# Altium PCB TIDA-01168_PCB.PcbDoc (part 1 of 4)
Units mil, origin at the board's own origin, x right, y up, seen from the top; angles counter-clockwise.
Board outline 7874.02 x 8344.02 mil, 4 copper layers (Top Layer, Signal Layer 1, Signal Layer 2, Bottom Layer), stack 65.748 mil thick; 480 components, 223 nets, 1266 pads, 1791 vias.
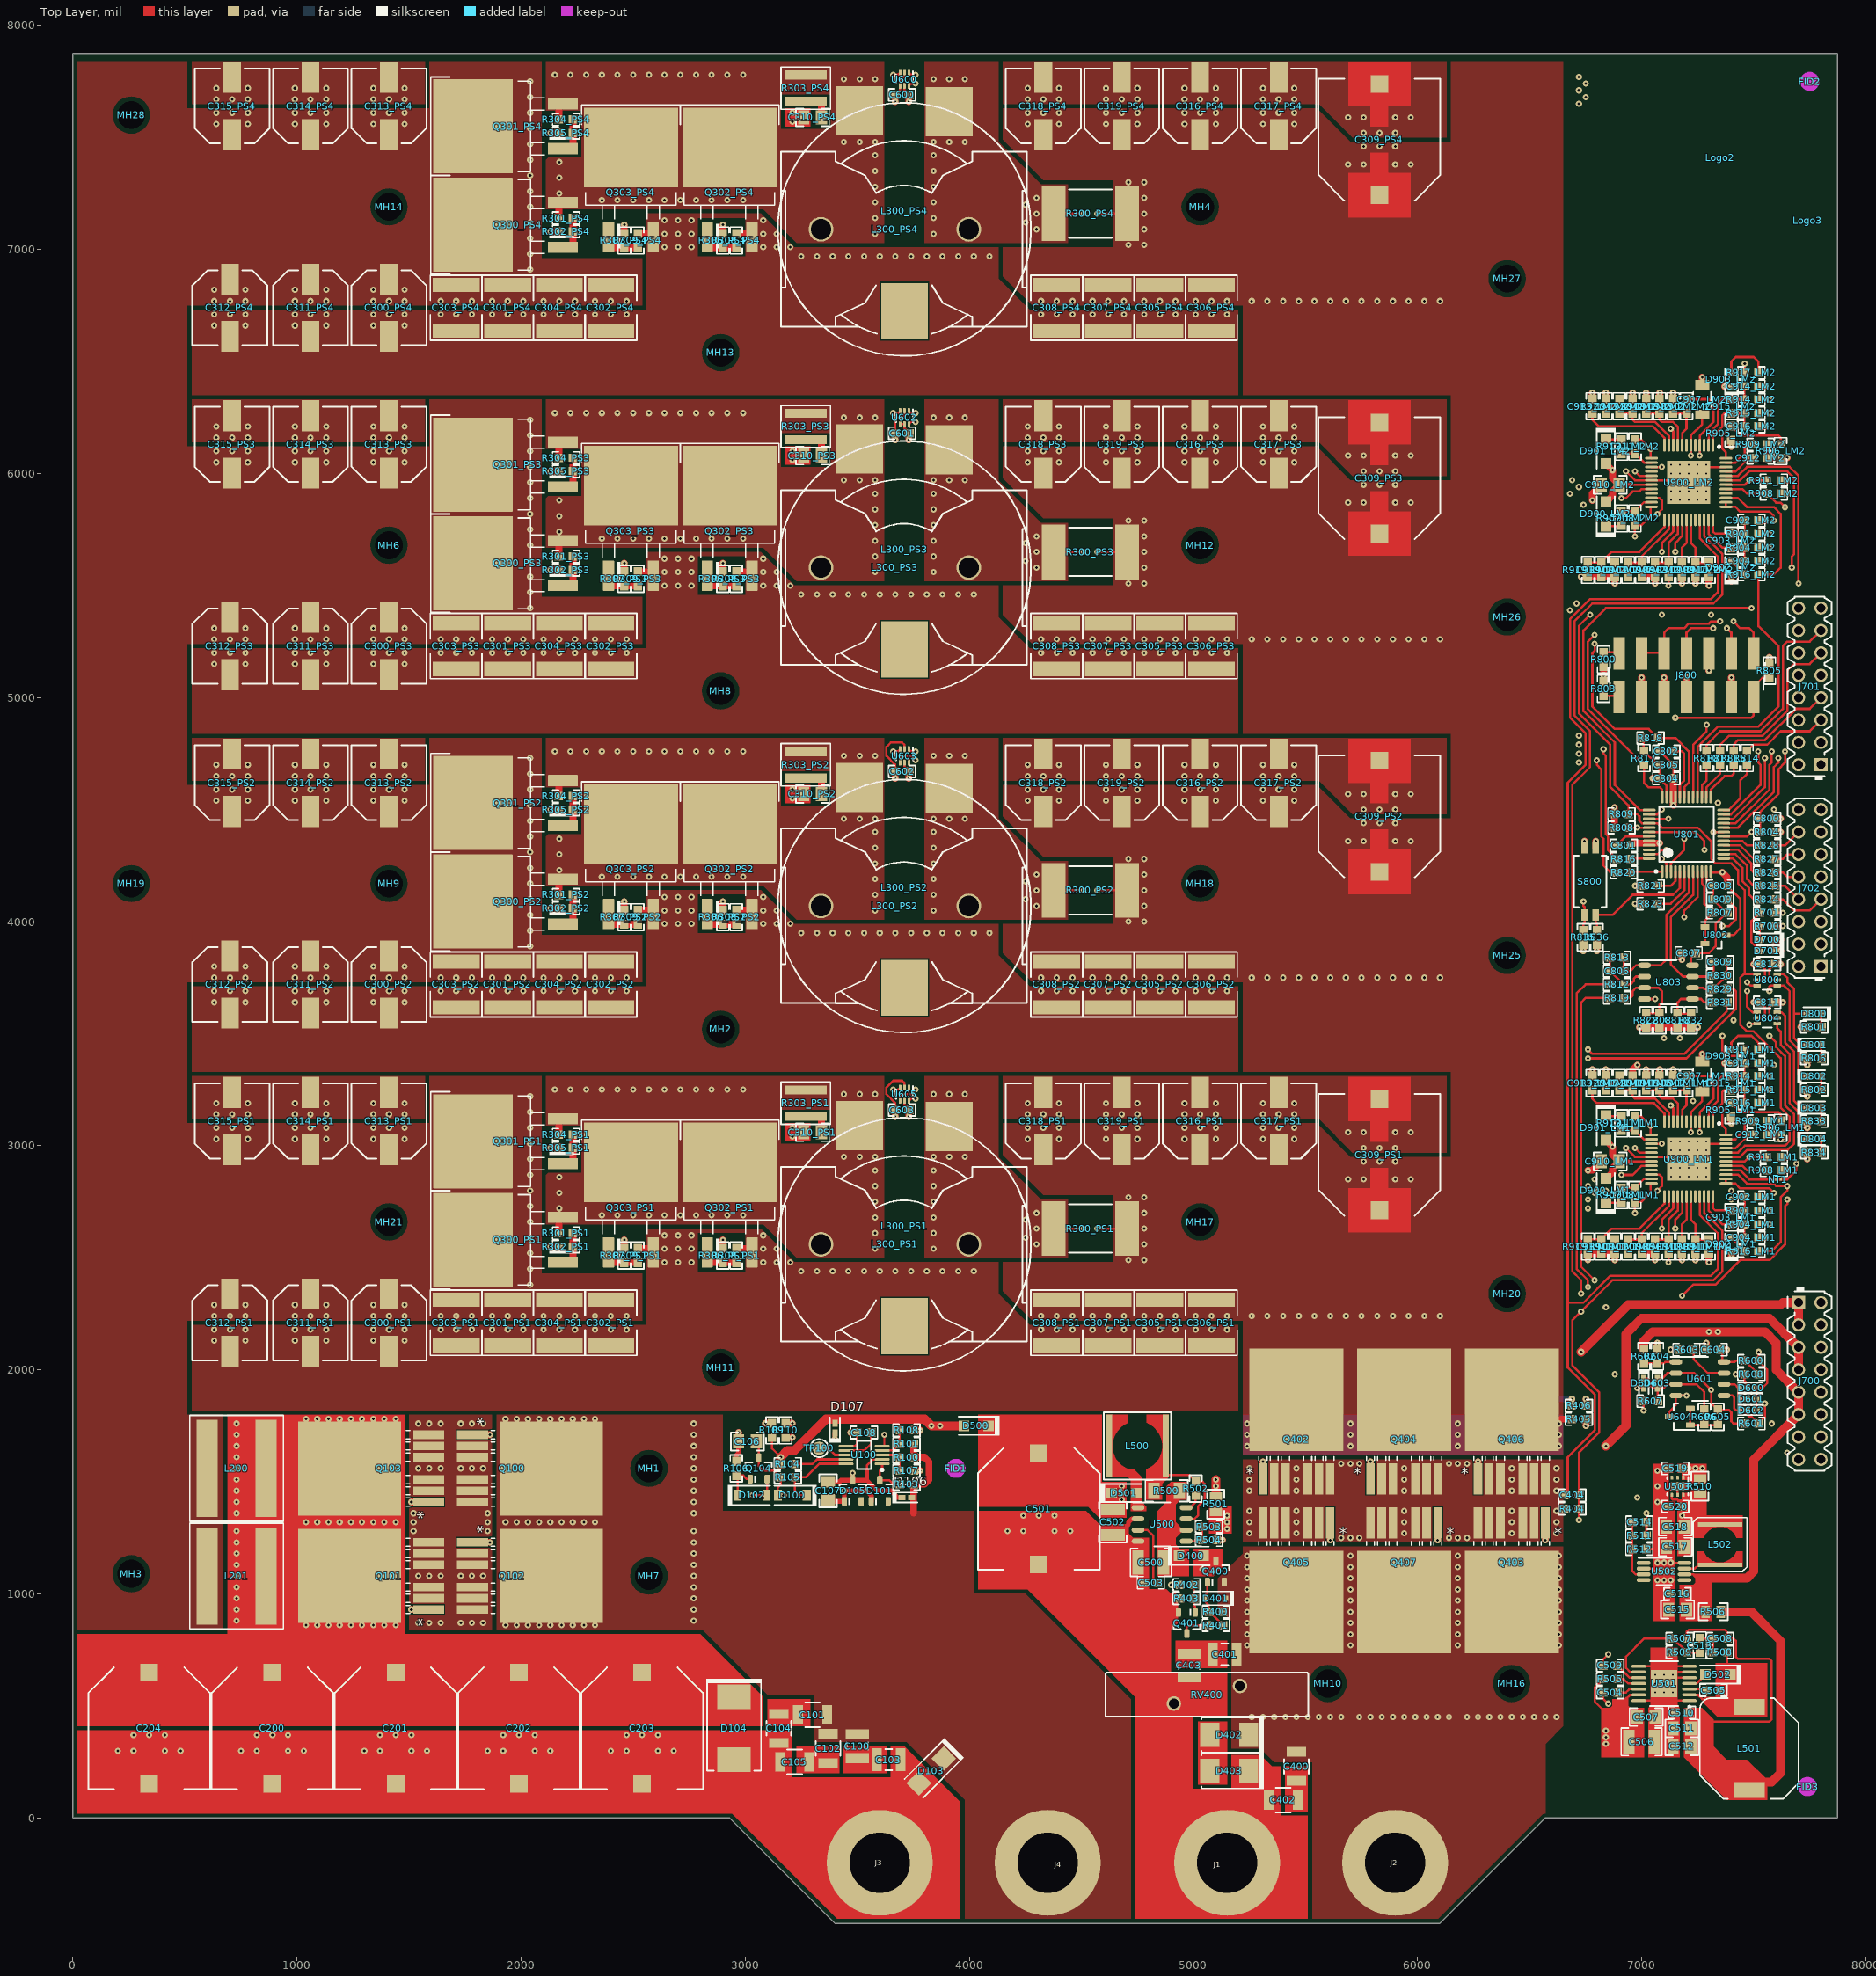
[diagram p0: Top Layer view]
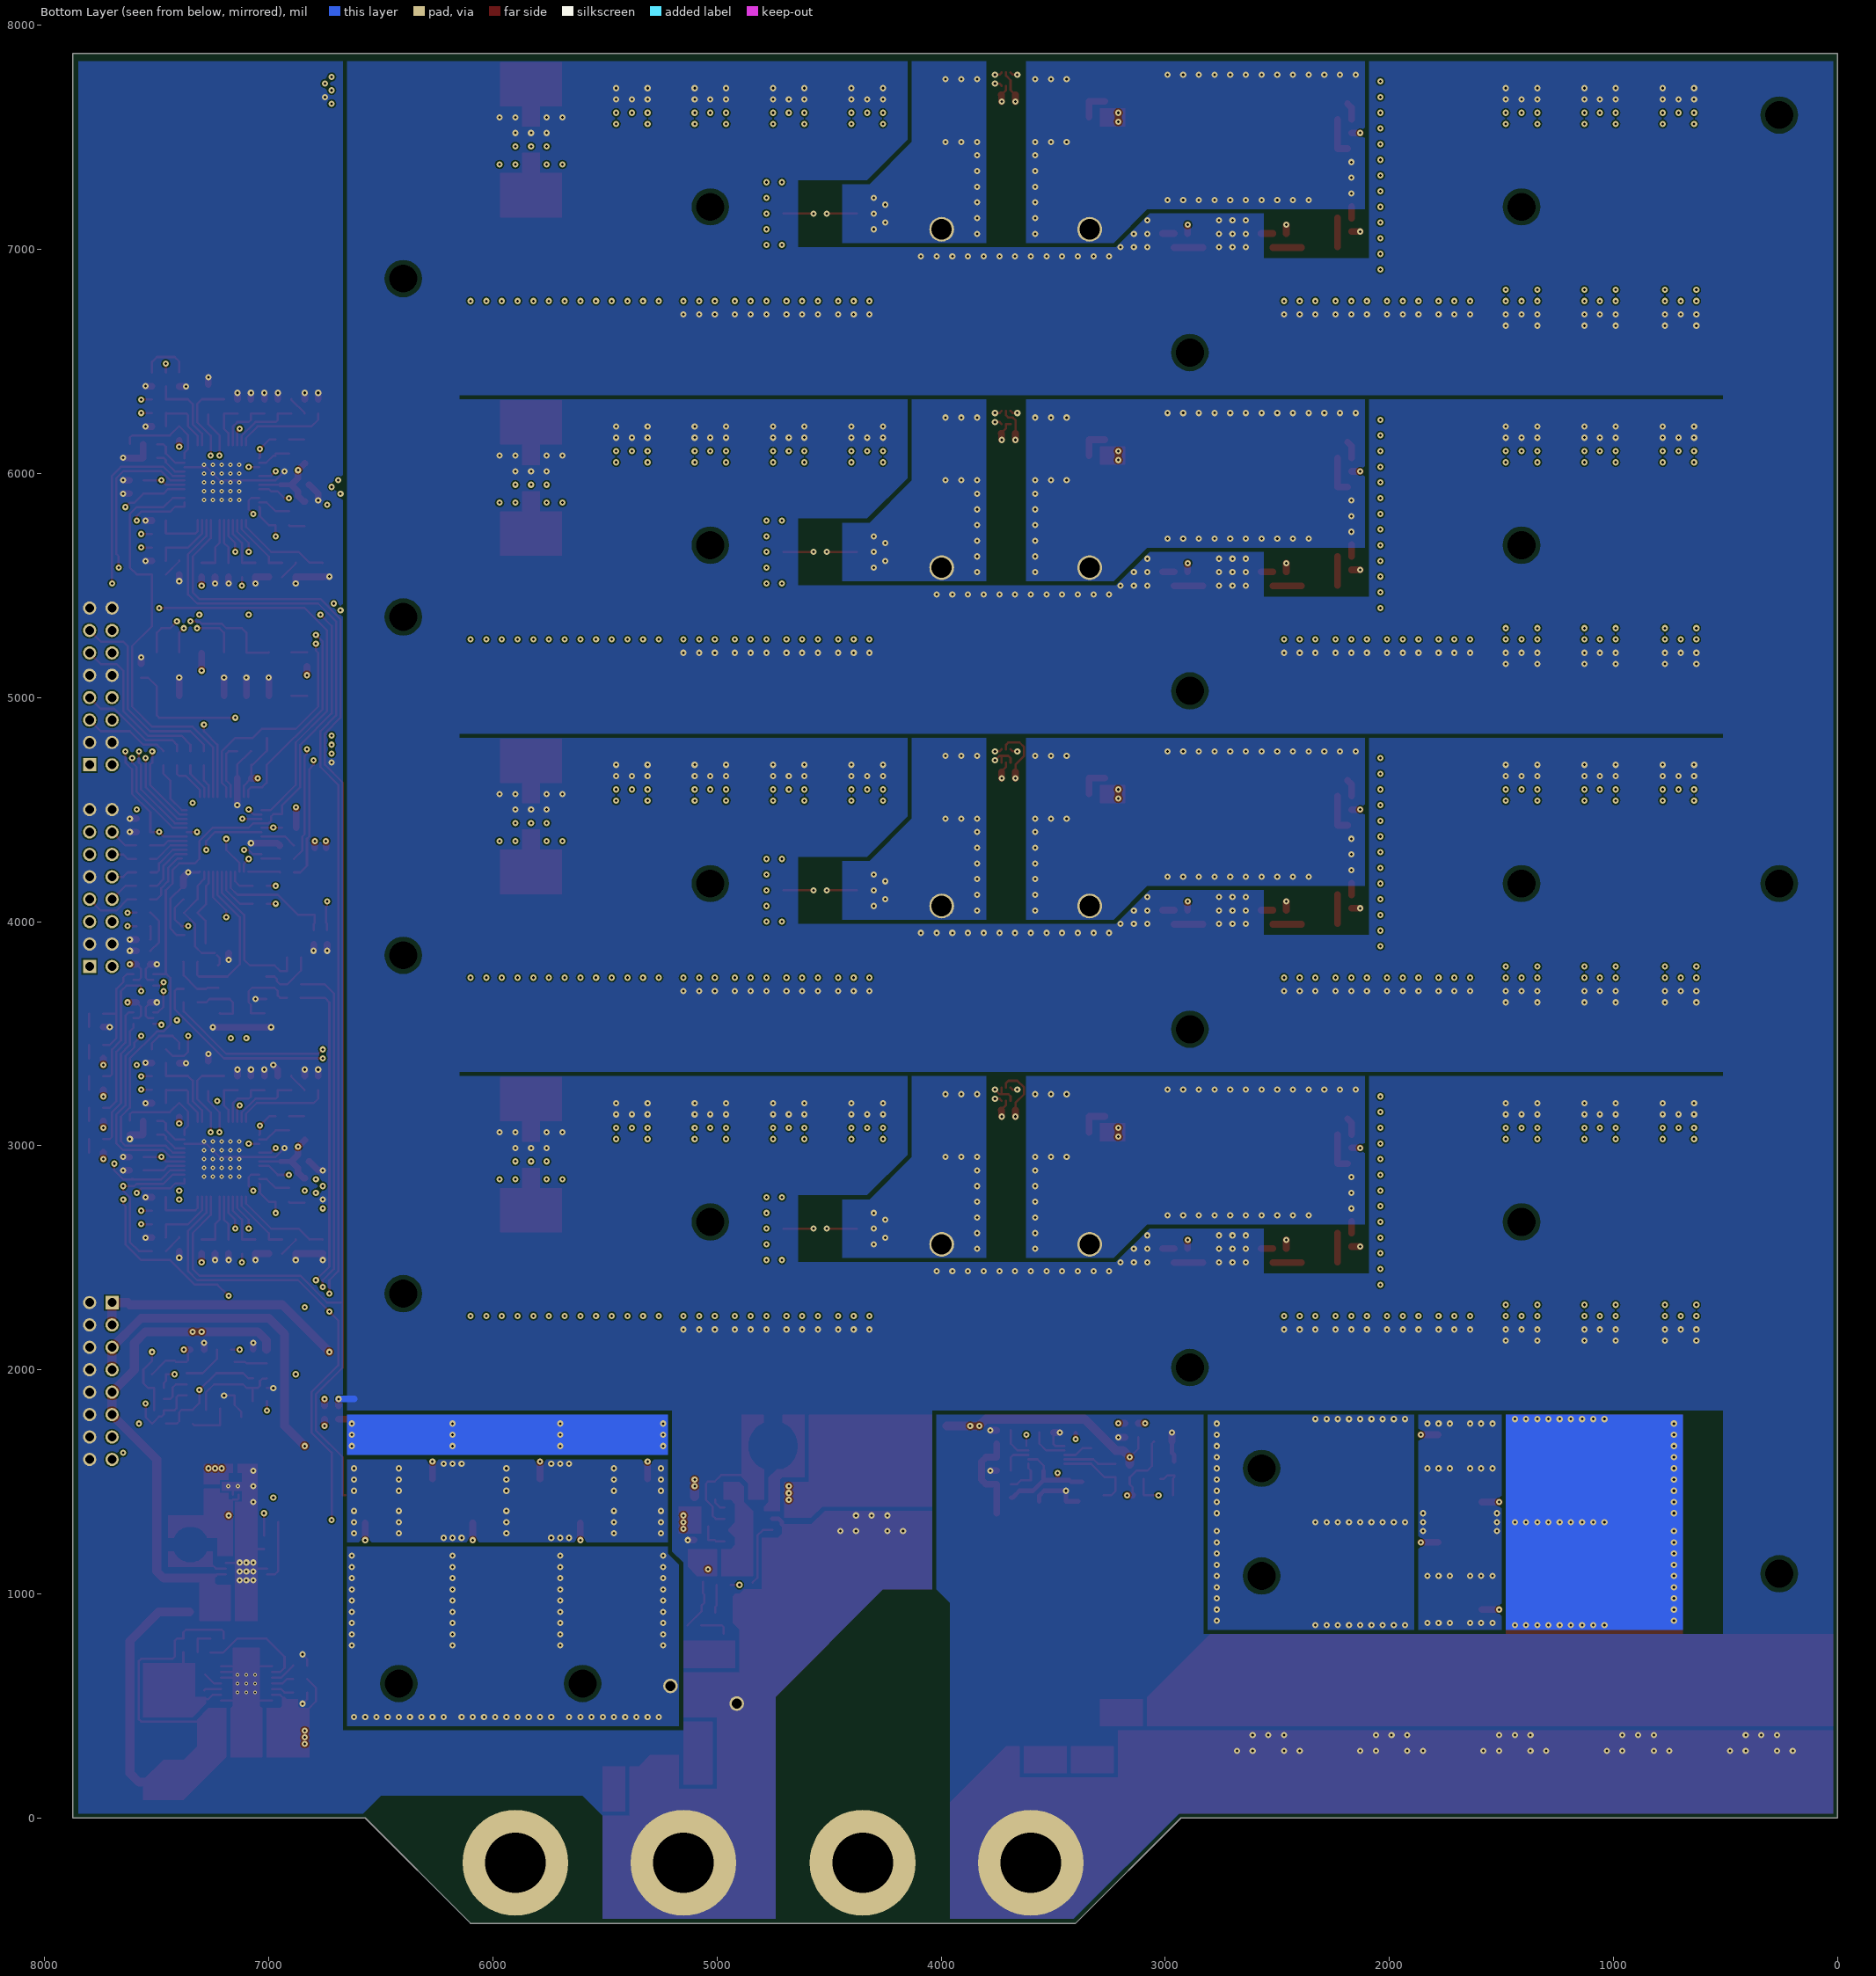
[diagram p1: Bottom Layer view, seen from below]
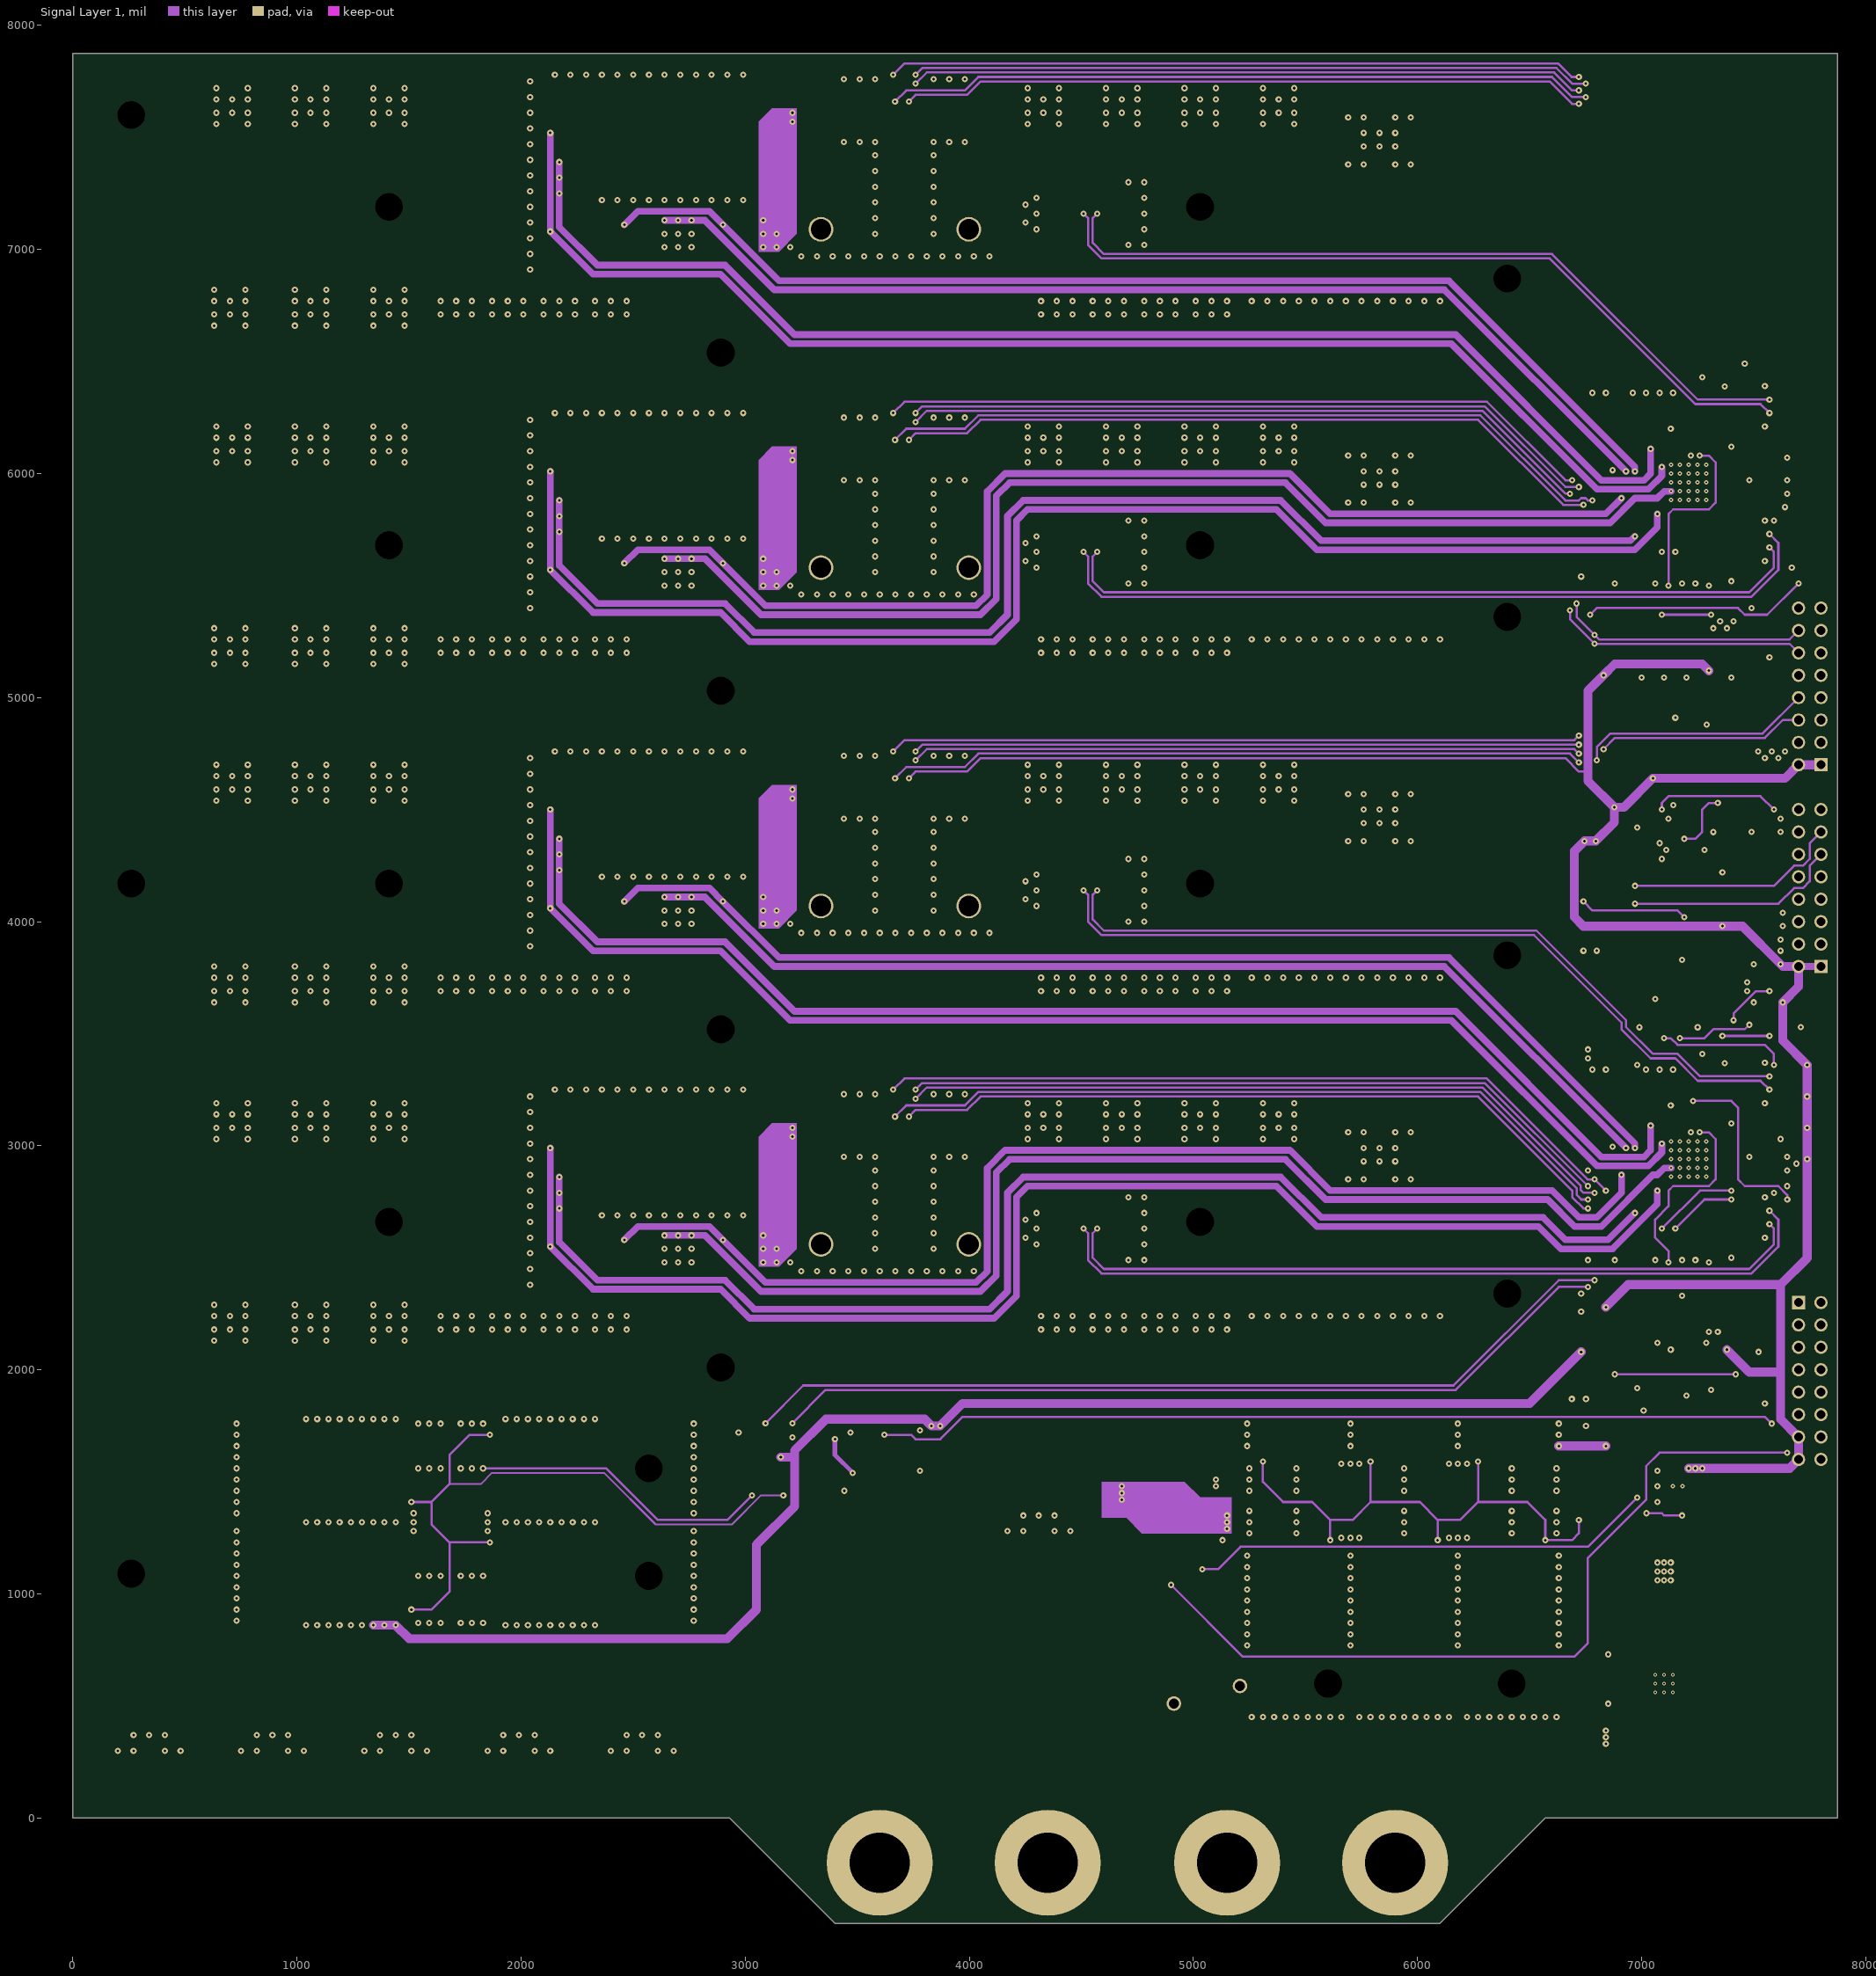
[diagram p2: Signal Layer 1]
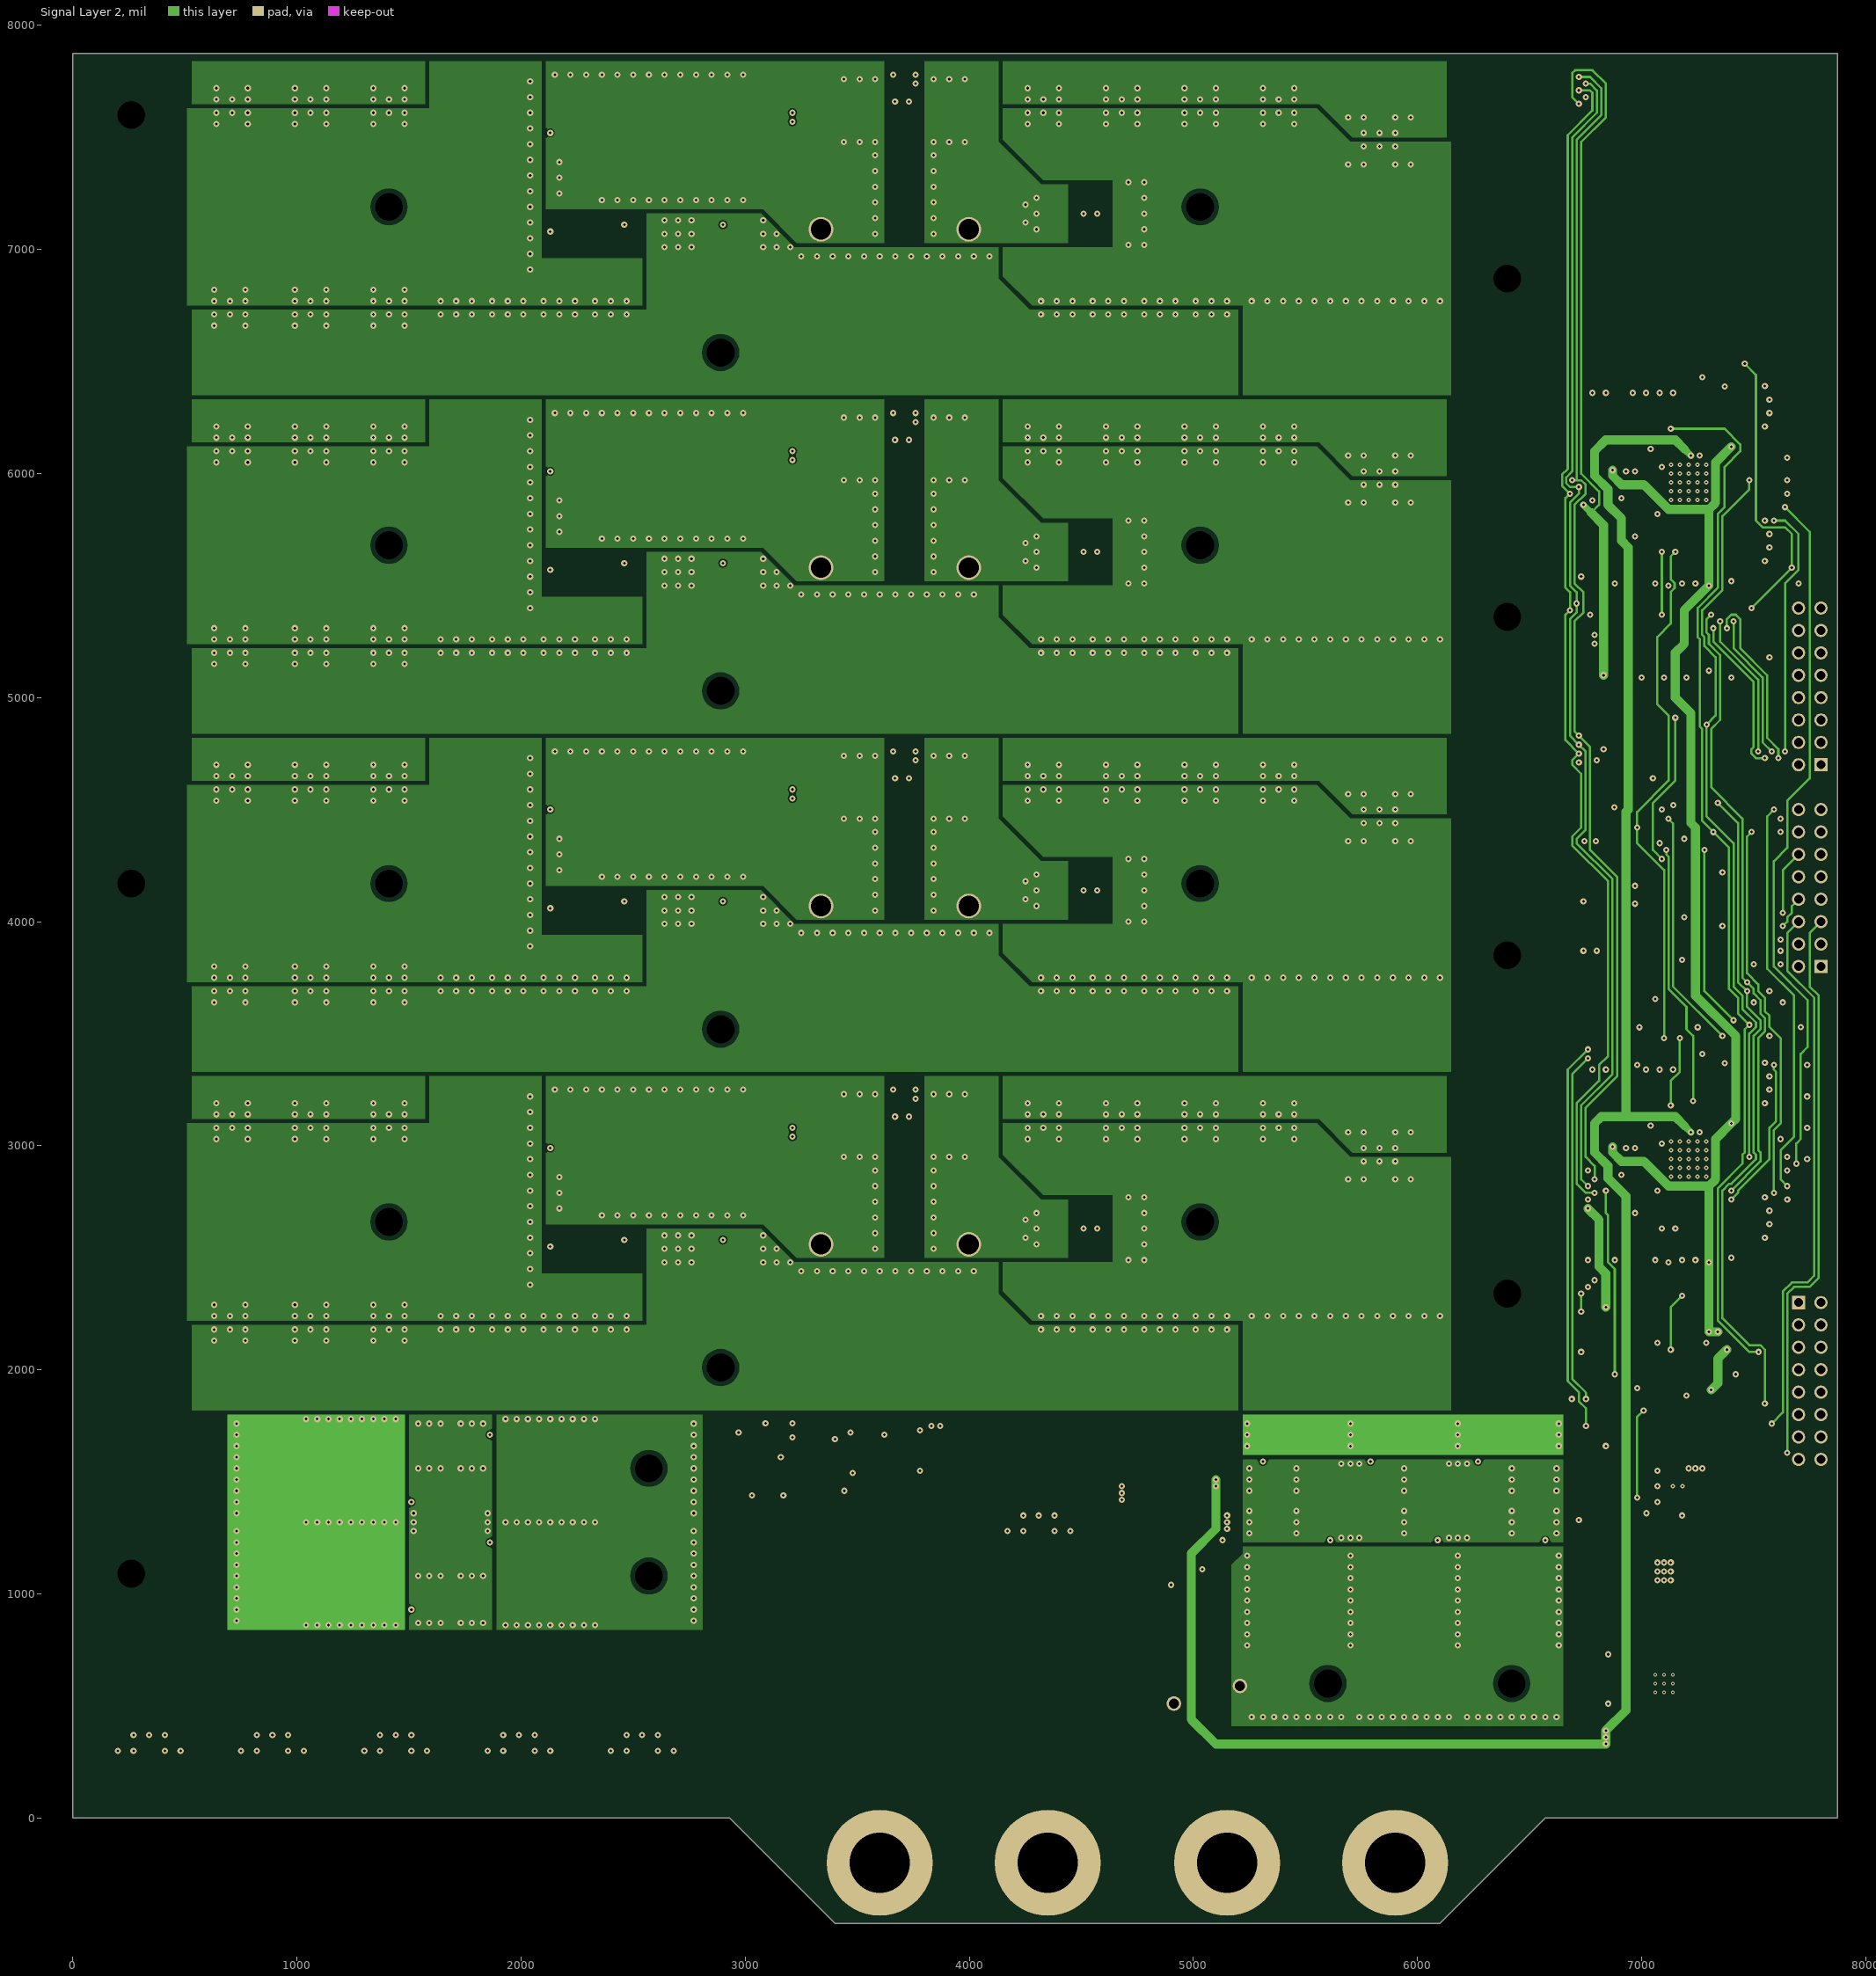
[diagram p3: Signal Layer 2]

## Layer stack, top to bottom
Top Solder: solder mask 0.4, Solder Resist, Dk 3.5
Top Layer: signal copper 3.7402
Dielectric1: prepreg 13.7795, 2x 7628, Dk 4.2
Signal Layer 1: signal copper 1.378
Dielectric 3: core 27.9528, FR-4, Dk 4.2
Signal Layer 2: signal copper 1.378
Dielectric 2: prepreg 13.7795, 2x 7628, Dk 4.2
Bottom Layer: signal copper 3.7402
Bottom Solder: solder mask 0.4, Solder Resist, Dk 3.5

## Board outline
0,0 2930,0 3400,-470 6100,-470 6570,0 7874.02,0 7874.02,7874.02 0,7874.02

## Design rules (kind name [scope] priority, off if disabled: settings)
AcuteAngle [All] p1: minimum=4.50000000000000E+0001 checktracksonly=TRUE
AssemblyTestPointUsage [All] p1: valid=2
BoardOutlineClearance BoardOutlineClearance_MountingHoles [OnCopper and InComponentClass('Mounting Holes')] p1: gap=40
BoardOutlineClearance BoardOutlineClearance_Poly [OnCopper and IsPoly] p2: gap=20
BoardOutlineClearance [OnCopper and Not InComponentClass('Logo') and not InComponentClass('FiducialMark') and not InRegion(1000,500,4000,800) and not InPoly] p3: gap=20
Clearance Clearance_hole_to_copper [InPadClass('NPTH')] p1: gap=20
Clearance Clearance_Keepouts [((IsTrack Or IsArc) And Not InPoly) And IsFree and IsKeepOut vs ((IsTrack Or IsArc) And Not InPoly) And IsFree and IsKeepOut] p2: gap=0
Clearance Clearance_Poly [InPolygon] p3: gap=6
Clearance [All] p4: gap=6
ComponentClearance ComponentClearance_MountingHoles_FiducialMarks [InComponentClass('Mounting Holes') vs InComponentClass('FiducialMark')] p1 off: gap=50 collisioncheckmode=3 verticalgap=10 showdistances=FALSE
ComponentClearance ComponentClearance_Shunt [InComponentClass('Header') vs InComponentClass('Shunt')] p2 off: gap=0 collisioncheckmode=3 verticalgap=0 showdistances=FALSE
ComponentClearance ComponentClearance_Logo [InComponentClass('Logo')] p3 off: gap=50 collisioncheckmode=3 verticalgap=10 showdistances=FALSE
ComponentClearance ComponentClearance_ScrewToNut [(HasFootprint('NY PMS 440 0025 PH')) vs (HasFootprint('Keystone_1902C'))] p4 off: gap=5 collisioncheckmode=3 verticalgap=10 showdistances=FALSE
ComponentClearance ComponentClearance_MountingHoles [InComponentClass('Mounting Holes')] p5 off: gap=250 collisioncheckmode=3 verticalgap=100000 showdistances=FALSE
ComponentClearance ComponentClearance_SmallPassives [HasFootprint('0201*') or HasFootprint('0402*') or HasFootprint('0508') or HasFootprint('0603*') or HasFootprint('0612') or HasFootprint('0805*') or HasFootprint('0815*') or HasFootprint('0830*') or HasFootprint('1206*') or HasFootprint('1210*') or HasFootprint('1808*') or HasFootprint('1812*') or HasFootprint('1825*') or HasFootprint('2010*') or HasFootprint('2220*') or HasFootprint('2225*') or HasFootprint('2512*') or HasFootprint('2728*') or HasFootprint('3518*') vs HasFootprint('0201*') or HasFootprint('0402*') or HasFootprint('0508') or HasFootprint('0603*') or HasFootprint('0612') or HasFootprint('0805*') or HasFootprint('0815*') or HasFootprint('0830*') or HasFootprint('1206*') or HasFootprint('1210*') or HasFootprint('1808*') or HasFootprint('1812*') or HasFootprint('1825*') or HasFootprint('2010*') or HasFootprint('2220*') or HasFootprint('2225*') or HasFootprint('2512*') or HasFootprint('2728*') or HasFootprint('3518*')] p6 off: gap=14.96 collisioncheckmode=3 verticalgap=10 showdistances=FALSE
ComponentClearance ComponentClearance_THtoSMT [IsThruComponent vs IsSMTComponent] p7 off: gap=40 collisioncheckmode=3 verticalgap=30 showdistances=FALSE
ComponentClearance ComponentClearance_THtoTH [IsThruComponent vs IsThruComponent] p8 off: gap=30 collisioncheckmode=3 verticalgap=30 showdistances=FALSE
ComponentClearance [All] p9 off: gap=30 collisioncheckmode=3 verticalgap=10 showdistances=FALSE
DiffPairsRouting [All] p1: maxlimit=100 minlimit=10 mostfreqgap=10 toplayer_minwidth=15 toplayer_maxwidth=15 toplayer_prefwidth=15 midlayer1_minwidth=15 midlayer1_maxwidth=15 midlayer1_prefwidth=15 midlayer2_minwidth=15 midlayer2_maxwidth=15 midlayer2_prefwidth=15 bottomlayer_minwidth=15 bottomlayer_maxwidth=15 bottomlayer_prefwidth=15 maxuncoupledlength=1000
FabricationTestPointUsage TestPointUsage [All] p1: valid=2 allowmultiple=FALSE
FabricationTestpoint Testpoint [All] p1: side=3 testpointundercomponent=TRUE minsize=40 maxsize=100 preferedsize=60 minholesize=0 maxholesize=40 preferedholesize=32 testpointgrid=1 allowsidetop=TRUE allowsidebottom=TRUE usegrid=TRUE gridtolerance=0.01
FanoutControl Fanout_LCC [IsLCC] p1: bgadir=Out bgaviamode=Centered fanoutstyle=Auto fanoutdirection=Alternating viagrid=1 // Fanout_LCC (Default Rule)
FanoutControl Fanout_BGA [IsBGA] p2: bgadir=Out bgaviamode=Centered fanoutstyle=Auto fanoutdirection=Alternating viagrid=1 // Fanout_BGA (Default Rule)
FanoutControl Fanout_Default [All] p4: bgadir=Out bgaviamode=Centered fanoutstyle=Auto fanoutdirection=Alternating viagrid=1 // Fanout_Default (Default Rule)
FanoutControl Fanout_Small [(CompPinCount < 5)] p5: bgadir=Out bgaviamode=Centered fanoutstyle=Auto fanoutdirection=OutThenIn viagrid=1 // Fanout_Small (Default Rule)
Height [All] p1 off: minheight=0 maxheight=1000 prefheight=500
HoleSize [All] p1: absolutevalues=TRUE maxlimit=270 minlimit=7.87 maxpercent=80.000 minpercent=20.000
MinimumAnnularRing MinimumAnnularRing_ThermalPadVias [IsVia and InAnyComponent] p1: minimumring=3.5
MinimumAnnularRing [All] p2: minimumring=8
MinimumSolderMaskSliver MinimumSolderMaskSliver_Logo [InComponentClass('Logo') vs InComponentClass('Logo')] p1: minsoldermaskwidth=0.7
MinimumSolderMaskSliver [Not IsVia vs Not IsVia] p2: minsoldermaskwidth=3.94
PlaneConnect [All] p1: planeconnectstyle=Direct reliefexpansion=10 reliefentries=4 reliefconductorwidth=10 reliefairgap=10
PolygonConnect [All] p1: connectstyle=Direct reliefconductorwidth=10 reliefentries=4 polygonreliefangle="90 Angle" airgapwidth=10
RoomDefinition 12-V-CircuitBreaker [InComponentClass('12-V-CircuitBreaker')] p1 off: confinementstyle=ConfineIn formatcopy=TRUE lockcomponents=FALSE outline 4040,700 6630,700 6630,1800 4040,1800
RoomDefinition 48-V-CircuitBreaker [InComponentClass('48-V-CircuitBreaker')] p2 off: confinementstyle=ConfineIn formatcopy=TRUE lockcomponents=FALSE outline 980,840 2800,840 2800,1370 4020,1370 4020,1800 980,1800
RoomDefinition 48-V-Filter [InComponentClass('48-V-Filter')] p3 off: confinementstyle=ConfineIn formatcopy=TRUE lockcomponents=FALSE outline 0,0 2800,0 2800,820 960,820 960,1800 0,1800
RoomDefinition Bias [InComponentClass('Bias')] p4 off: confinementstyle=ConfineIn formatcopy=TRUE lockcomponents=FALSE outline 6650,0 7870,0 7870,1620 6650,1620
RoomDefinition PS1 [InComponentClass('PS1')] p5 off: confinementstyle=ConfineIn formatcopy=FALSE lockcomponents=FALSE outline 530,1820 6130,1820 6130,3310 530,3310
RoomDefinition PS4 [InComponentClass('PS4')] p6 off: confinementstyle=ConfineIn formatcopy=FALSE lockcomponents=FALSE outline 530,6350 6130,6350 6130,7840 530,7840
RoomDefinition PS3 [InComponentClass('PS3')] p7 off: confinementstyle=ConfineIn formatcopy=FALSE lockcomponents=FALSE outline 530,4840 6130,4840 6130,6330 530,6330
RoomDefinition PS2 [InComponentClass('PS2')] p8 off: confinementstyle=ConfineIn formatcopy=FALSE lockcomponents=FALSE outline 530,3330 6130,3330 6130,4820 530,4820
RoomDefinition LM2 [InComponentClass('LM2')] p9 off: confinementstyle=ConfineIn formatcopy=TRUE lockcomponents=FALSE outline 6650,5370 7750,5370 7750,6470 6650,6470
RoomDefinition LM1 [InComponentClass('LM1')] p10 off: confinementstyle=ConfineIn formatcopy=TRUE lockcomponents=FALSE outline 6650,2350 7750,2350 7750,3450 6650,3450
RoomDefinition IF [InComponentClass('IF')] p11 off: confinementstyle=ConfineIn formatcopy=TRUE lockcomponents=FALSE outline 7630,3730 7870,3730 7870,5350 7630,5350
RoomDefinition Diag [InComponentClass('Diag')] p12 off: confinementstyle=ConfineIn formatcopy=TRUE lockcomponents=FALSE outline 6650,1640 7640,1640 7640,2330 6650,2330
RoomDefinition Control [InComponentClass('Control')] p13 off: confinementstyle=ConfineIn formatcopy=TRUE lockcomponents=FALSE outline 6650,3470 7610,3470 7610,5350 6650,5350
RoutingVias ThermalPadVias [IsVia and InAnyComponent] p1: holewidth=7.87 width=19.68 viastyle="Through Hole" minholewidth=7.87 minwidth=15 maxholewidth=12.99 maxwidth=23.62
RoutingVias [All] p2: holewidth=16 width=34 viastyle="Through Hole" minholewidth=7.87 minwidth=26 maxholewidth=40 maxwidth=65
SilkToBoardRegionClearance [Not ((IsComment or IsDesignator) And (Hide <> 'False')) and not InRegion(1000,500,4000,800)] p1:
SilkToSilkClearance SilkToSilkClearance_Pb-FreeLogo [(HasFootprint('Pb-Free_Overlay_Medium') OR HasFootprint('Pb-Free_Overlay_Small')) vs (HasFootprint('Pb-Free_Overlay_Medium') OR HasFootprint('Pb-Free_Overlay_Small'))] p1 off: silktosilkclearance=0
SilkToSilkClearance [All] p2 off: silktosilkclearance=4
SilkToSolderMaskClearance SilkToComponentPadClearance [IsPad and InAnycomponent] p1 off: minsilkscreentomaskgap=5 clearancetoexposedcopper=TRUE
SilkToSolderMaskClearance "Silk to Solder Mask Opening" [All] p2 off: minsilkscreentomaskgap=4 clearancetoexposedcopper=FALSE
SolderMaskExpansion SolderMaskExpansion_Via_Tint [IsVia] p1: expansion=-10
SolderMaskExpansion [All] p2: expansion=1.97
Width [All] p1: maxlimit=100 minlimit=6 preferedwidth=10 checkconnectedcopper=TRUE
14 further rules are at their usual default settings.

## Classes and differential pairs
component class 12-V-CircuitBreaker: C400 C401 C402 C403 C404 D400 D401 D402 D403 Q400 Q401 Q402 Q403 Q404 Q405 Q406 Q407 R400 R401 R402 R403 R404 R405 R406 RV400
component class 48-V-CircuitBreaker: C100 C101 C102 C103 C104 C105 C106 C107 C108 D100 D101 D102 D103 D104 D105 D106 D107 Q100 Q101 Q102 Q103 Q104 R100 R101 R103 R104 R105 R106 R107 R108 R109 R110 TP100 U100
component class 48-V-Filter: C200 C201 C202 C203 C204 L200 L201
component class Bias: C500 C501 C502 C503 C504 C505 C506 C507 C508 C509 C510 C511 C512 C513 C514 C515 C516 C517 C518 C519 C520 D500 D501 D502 L500 L501 L502 R500 R501 R502 R503 R504 R505 R506 R507 R508 R509 R510 R511 R512 U500 U501 U502 U503
component class Control: C800 C801 C802 C803 C804 C805 C806 C807 C808 C809 C810 C811 C812 D800 D801 D802 D803 D804 J800 L800 R800 R801 R802 R803 R804 R805 R806 R807 R808 R809 R810 R811 R812 R813 R814 R815 R816 R817 R818 R819 R820 R821 R822 R823 R824 R825 R826 R827 R828 R829 R830 R831 R832 R833 R834 R835 R836 R841 R843 R844 S800 U800 U801 U802 U803 U804
component class Diag: C600 C601 C602 C603 C604 D600 D601 D602 D603 D604 R600 R601 R602 R603 R604 R605 R606 R607 R608 U600 U601 U602 U603 U604 U605
component class IF: D700 D701 J700 J701 J702 R700 R701
component class LM1: C900_LM1 C901_LM1 C902_LM1 C903_LM1 C904_LM1 C905_LM1 C906_LM1 C907_LM1 C908_LM1 C909_LM1 C910_LM1 C911_LM1 C912_LM1 C913_LM1 C914_LM1 C915_LM1 C916_LM1 C917_LM1 C918_LM1 C919_LM1 C920_LM1 D900_LM1 D901_LM1 D902_LM1 D903_LM1 R900_LM1 R901_LM1 R902_LM1 R903_LM1 R904_LM1 R905_LM1 R906_LM1 R907_LM1 R908_LM1 R909_LM1 R910_LM1 R911_LM1 R912_LM1 R913_LM1 R914_LM1 R915_LM1 R916_LM1 R917_LM1 R918_LM1 R919_LM1 R920_LM1 U900_LM1
component class LM2: C900_LM2 C901_LM2 C902_LM2 C903_LM2 C904_LM2 C905_LM2 C906_LM2 C907_LM2 C908_LM2 C909_LM2 C910_LM2 C911_LM2 C912_LM2 C913_LM2 C914_LM2 C915_LM2 C916_LM2 C917_LM2 C918_LM2 C919_LM2 C920_LM2 D900_LM2 D901_LM2 D902_LM2 D903_LM2 R900_LM2 R901_LM2 R902_LM2 R903_LM2 R904_LM2 R905_LM2 R906_LM2 R907_LM2 R908_LM2 R909_LM2 R910_LM2 R911_LM2 R912_LM2 R913_LM2 R914_LM2 R915_LM2 R916_LM2 R917_LM2 R918_LM2 R919_LM2 R920_LM2 U900_LM2
component class PS1: C300_PS1 C301_PS1 C302_PS1 C303_PS1 C304_PS1 C305_PS1 C306_PS1 C307_PS1 C308_PS1 C309_PS1 C310_PS1 C311_PS1 C312_PS1 C313_PS1 C314_PS1 C315_PS1 C316_PS1 C317_PS1 C318_PS1 C319_PS1 L300_PS1 Q300_PS1 Q301_PS1 Q302_PS1 Q303_PS1 R300_PS1 R301_PS1 R302_PS1 R303_PS1 R304_PS1 R305_PS1 R306_PS1 R307_PS1 R308_PS1 R309_PS1
component class PS2: C300_PS2 C301_PS2 C302_PS2 C303_PS2 C304_PS2 C305_PS2 C306_PS2 C307_PS2 C308_PS2 C309_PS2 C310_PS2 C311_PS2 C312_PS2 C313_PS2 C314_PS2 C315_PS2 C316_PS2 C317_PS2 C318_PS2 C319_PS2 L300_PS2 Q300_PS2 Q301_PS2 Q302_PS2 Q303_PS2 R300_PS2 R301_PS2 R302_PS2 R303_PS2 R304_PS2 R305_PS2 R306_PS2 R307_PS2 R308_PS2 R309_PS2
component class PS3: C300_PS3 C301_PS3 C302_PS3 C303_PS3 C304_PS3 C305_PS3 C306_PS3 C307_PS3 C308_PS3 C309_PS3 C310_PS3 C311_PS3 C312_PS3 C313_PS3 C314_PS3 C315_PS3 C316_PS3 C317_PS3 C318_PS3 C319_PS3 L300_PS3 Q300_PS3 Q301_PS3 Q302_PS3 Q303_PS3 R300_PS3 R301_PS3 R302_PS3 R303_PS3 R304_PS3 R305_PS3 R306_PS3 R307_PS3 R308_PS3 R309_PS3
component class PS4: C300_PS4 C301_PS4 C302_PS4 C303_PS4 C304_PS4 C305_PS4 C306_PS4 C307_PS4 C308_PS4 C309_PS4 C310_PS4 C311_PS4 C312_PS4 C313_PS4 C314_PS4 C315_PS4 C316_PS4 C317_PS4 C318_PS4 C319_PS4 L300_PS4 Q300_PS4 Q301_PS4 Q302_PS4 Q303_PS4 R300_PS4 R301_PS4 R302_PS4 R303_PS4 R304_PS4 R305_PS4 R306_PS4 R307_PS4 R308_PS4 R309_PS4
channel class TIDA-01168_LM5170_Subsystem: LM1 LM2
channel class TIDA-01168_Power_Stage: PS1 PS2 PS3 PS4
pad class NPTH: MH1-1 MH2-1 MH3-1 MH4-1 MH6-1 MH7-1 MH8-1 MH9-1 MH10-1 MH11-1 MH12-1 MH13-1 MH14-1 MH16-1 MH17-1 MH18-1 MH19-1 MH20-1 MH21-1 MH25-1 MH26-1 MH27-1 MH28-1

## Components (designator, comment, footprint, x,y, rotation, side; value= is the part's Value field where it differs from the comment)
C100 "CGA6M2X7R2A474K200AA" 1210_220L 3500,320 r270 top
C101 "CGA6P3X7S1H106K250AB" 1210_280 3300,460 r180 top
C102 "CGA6P3X7S1H106K250AB" 1210_280 3370,310 r270 top
C103 "CGA6M2X7R2A474K200AA" 1210_220L 3640,260 r0 top
C104 "CGA6P3X7S1H106K250AB" 1210_280 3150,400 r270 top
C105 "CGA6P3X7S1H106K250AB" 1210_280 3220,250 r180 top
C106 "GRM21BR72A103KA01L" 0805_HV 3010,1680 r180 top
C107 "GRM21BR72A103KA01L" 0805_HV 3370,1460 r270 top
C108 "GCM188R71E473KA37D" 0603 3530,1720 r180 top
C200 "UCZ1K151MNQ1MS" UCZ_1250x1350 890,400 r270 top
C201 "UCZ1K151MNQ1MS" UCZ_1250x1350 1440,400 r270 top
C202 "UCZ1K151MNQ1MS" UCZ_1250x1350 1990,400 r270 top
C203 "UCZ1K151MNQ1MS" UCZ_1250x1350 2540,400 r270 top
C204 "UCZ1K151MNQ1MS" UCZ_1250x1350 340,400 r270 top
C300_PS1 "PCV1J390MCL2GS" PCV_800x1200 1410,2210 r270 top (schematic designator C300)
C300_PS2 "PCV1J390MCL2GS" PCV_800x1200 1410,3720 r270 top (schematic designator C300)
C300_PS3 "PCV1J390MCL2GS" PCV_800x1200 1410,5230 r270 top (schematic designator C300)
C300_PS4 "PCV1J390MCL2GS" PCV_800x1200 1410,6740 r270 top (schematic designator C300)
C301_PS1 "CGA9N2X7R2A475M230KA" 2220_250 1940,2210 r270 top (schematic designator C301)
C301_PS2 "CGA9N2X7R2A475M230KA" 2220_250 1940,3720 r270 top (schematic designator C301)
C301_PS3 "CGA9N2X7R2A475M230KA" 2220_250 1940,5230 r270 top (schematic designator C301)
C301_PS4 "CGA9N2X7R2A475M230KA" 2220_250 1940,6740 r270 top (schematic designator C301)
C302_PS1 "CGA9N2X7R2A475M230KA" 2220_250 2400,2210 r270 top (schematic designator C302)
C302_PS2 "CGA9N2X7R2A475M230KA" 2220_250 2400,3720 r270 top (schematic designator C302)
C302_PS3 "CGA9N2X7R2A475M230KA" 2220_250 2400,5230 r270 top (schematic designator C302)
C302_PS4 "CGA9N2X7R2A475M230KA" 2220_250 2400,6740 r270 top (schematic designator C302)
C303_PS1 "CGA9N2X7R2A475M230KA" 2220_250 1710,2210 r270 top (schematic designator C303)
C303_PS2 "CGA9N2X7R2A475M230KA" 2220_250 1710,3720 r270 top (schematic designator C303)
C303_PS3 "CGA9N2X7R2A475M230KA" 2220_250 1710,5230 r270 top (schematic designator C303)
C303_PS4 "CGA9N2X7R2A475M230KA" 2220_250 1710,6740 r270 top (schematic designator C303)
C304_PS1 "CGA9N2X7R2A475M230KA" 2220_250 2170,2210 r270 top (schematic designator C304)
C304_PS2 "CGA9N2X7R2A475M230KA" 2220_250 2170,3720 r270 top (schematic designator C304)
C304_PS3 "CGA9N2X7R2A475M230KA" 2220_250 2170,5230 r270 top (schematic designator C304)
C304_PS4 "CGA9N2X7R2A475M230KA" 2220_250 2170,6740 r270 top (schematic designator C304)
C305_PS1 "CGA9N2X7R2A475M230KA" 2220_250 4850,2210 r270 top (schematic designator C305)
C305_PS2 "CGA9N2X7R2A475M230KA" 2220_250 4850,3720 r270 top (schematic designator C305)
C305_PS3 "CGA9N2X7R2A475M230KA" 2220_250 4850,5230 r270 top (schematic designator C305)
C305_PS4 "CGA9N2X7R2A475M230KA" 2220_250 4850,6740 r270 top (schematic designator C305)
C306_PS1 "CGA9N2X7R2A475M230KA" 2220_250 5080,2210 r270 top (schematic designator C306)
C306_PS2 "CGA9N2X7R2A475M230KA" 2220_250 5080,3720 r270 top (schematic designator C306)
C306_PS3 "CGA9N2X7R2A475M230KA" 2220_250 5080,5230 r270 top (schematic designator C306)
C306_PS4 "CGA9N2X7R2A475M230KA" 2220_250 5080,6740 r270 top (schematic designator C306)
C307_PS1 "CGA9N2X7R2A475M230KA" 2220_250 4620,2210 r270 top (schematic designator C307)
C307_PS2 "CGA9N2X7R2A475M230KA" 2220_250 4620,3720 r270 top (schematic designator C307)
C307_PS3 "CGA9N2X7R2A475M230KA" 2220_250 4620,5230 r270 top (schematic designator C307)
C307_PS4 "CGA9N2X7R2A475M230KA" 2220_250 4620,6740 r270 top (schematic designator C307)
C308_PS1 "CGA9N2X7R2A475M230KA" 2220_250 4390,2210 r270 top (schematic designator C308)
C308_PS2 "CGA9N2X7R2A475M230KA" 2220_250 4390,3720 r270 top (schematic designator C308)
C308_PS3 "CGA9N2X7R2A475M230KA" 2220_250 4390,5230 r270 top (schematic designator C308)
C308_PS4 "CGA9N2X7R2A475M230KA" 2220_250 4390,6740 r270 top (schematic designator C308)
C309_PS1 "UCZ1J181MNQ1MS" UCZ_1250x1350 5830,2960 r90 top (schematic designator C309)
C309_PS2 "UCZ1J181MNQ1MS" UCZ_1250x1350 5830,4470 r90 top (schematic designator C309)
C309_PS3 "UCZ1J181MNQ1MS" UCZ_1250x1350 5830,5980 r90 top (schematic designator C309)
C309_PS4 "UCZ1J181MNQ1MS" UCZ_1250x1350 5830,7490 r90 top (schematic designator C309)
C310_PS1 "GCM2165C2A101JA16D" 0805_HV 3300,3060 r180 top (schematic designator C310)
C310_PS2 "GCM2165C2A101JA16D" 0805_HV 3300,4570 r180 top (schematic designator C310)
C310_PS3 "GCM2165C2A101JA16D" 0805_HV 3300,6080 r180 top (schematic designator C310)
C310_PS4 "GCM2165C2A101JA16D" 0805_HV 3300,7590 r180 top (schematic designator C310)
C311_PS1 "PCV1J390MCL2GS" PCV_800x1200 1060,2210 r270 top (schematic designator C311)
C311_PS2 "PCV1J390MCL2GS" PCV_800x1200 1060,3720 r270 top (schematic designator C311)
C311_PS3 "PCV1J390MCL2GS" PCV_800x1200 1060,5230 r270 top (schematic designator C311)
C311_PS4 "PCV1J390MCL2GS" PCV_800x1200 1060,6740 r270 top (schematic designator C311)
C312_PS1 "PCV1J390MCL2GS" PCV_800x1200 700,2210 r270 top (schematic designator C312)
C312_PS2 "PCV1J390MCL2GS" PCV_800x1200 700,3720 r270 top (schematic designator C312)
C312_PS3 "PCV1J390MCL2GS" PCV_800x1200 700,5230 r270 top (schematic designator C312)
C312_PS4 "PCV1J390MCL2GS" PCV_800x1200 700,6740 r270 top (schematic designator C312)
C313_PS1 "PCV1J390MCL2GS" PCV_800x1200 1410,3110 r90 top (schematic designator C313)
C313_PS2 "PCV1J390MCL2GS" PCV_800x1200 1410,4620 r90 top (schematic designator C313)
C313_PS3 "PCV1J390MCL2GS" PCV_800x1200 1410,6130 r90 top (schematic designator C313)
C313_PS4 "PCV1J390MCL2GS" PCV_800x1200 1410,7640 r90 top (schematic designator C313)
C314_PS1 "PCV1J390MCL2GS" PCV_800x1200 1060,3110 r90 top (schematic designator C314)
C314_PS2 "PCV1J390MCL2GS" PCV_800x1200 1060,4620 r90 top (schematic designator C314)
C314_PS3 "PCV1J390MCL2GS" PCV_800x1200 1060,6130 r90 top (schematic designator C314)
C314_PS4 "PCV1J390MCL2GS" PCV_800x1200 1060,7640 r90 top (schematic designator C314)
C315_PS1 "PCV1J390MCL2GS" PCV_800x1200 710,3110 r90 top (schematic designator C315)
C315_PS2 "PCV1J390MCL2GS" PCV_800x1200 710,4620 r90 top (schematic designator C315)
C315_PS3 "PCV1J390MCL2GS" PCV_800x1200 710,6130 r90 top (schematic designator C315)
C315_PS4 "PCV1J390MCL2GS" PCV_800x1200 710,7640 r90 top (schematic designator C315)
C316_PS1 "PCV1J390MCL2GS" PCV_800x1200 5030,3110 r90 top (schematic designator C316)
C316_PS2 "PCV1J390MCL2GS" PCV_800x1200 5030,4620 r90 top (schematic designator C316)
C316_PS3 "PCV1J390MCL2GS" PCV_800x1200 5030,6130 r90 top (schematic designator C316)
C316_PS4 "PCV1J390MCL2GS" PCV_800x1200 5030,7640 r90 top (schematic designator C316)
C317_PS1 "PCV1J390MCL2GS" PCV_800x1200 5380,3110 r90 top (schematic designator C317)
C317_PS2 "PCV1J390MCL2GS" PCV_800x1200 5380,4620 r90 top (schematic designator C317)
C317_PS3 "PCV1J390MCL2GS" PCV_800x1200 5380,6130 r90 top (schematic designator C317)
C317_PS4 "PCV1J390MCL2GS" PCV_800x1200 5380,7640 r90 top (schematic designator C317)
C318_PS1 "PCV1J390MCL2GS" PCV_800x1200 4330,3110 r90 top (schematic designator C318)
C318_PS2 "PCV1J390MCL2GS" PCV_800x1200 4330,4620 r90 top (schematic designator C318)
C318_PS3 "PCV1J390MCL2GS" PCV_800x1200 4330,6130 r90 top (schematic designator C318)
C318_PS4 "PCV1J390MCL2GS" PCV_800x1200 4330,7640 r90 top (schematic designator C318)
C319_PS1 "PCV1J390MCL2GS" PCV_800x1200 4680,3110 r90 top (schematic designator C319)
C319_PS2 "PCV1J390MCL2GS" PCV_800x1200 4680,4620 r90 top (schematic designator C319)
C319_PS3 "PCV1J390MCL2GS" PCV_800x1200 4680,6130 r90 top (schematic designator C319)
C319_PS4 "PCV1J390MCL2GS" PCV_800x1200 4680,7640 r90 top (schematic designator C319)
C400 "CGA6P3X7S1H106K250AB" 1210_280 5460,230 r270 top
C401 "CGA6M2X7R2A474K200AA" 1210_220L 5140,730 r180 top
C402 "CGA6P3X7S1H106K250AB" 1210_280 5400,80 r180 top
C403 "CGA6M2X7R2A474K200AA" 1210_220L 4980,680 r270 top
C404 "GCM1885C1H680JA16D" 0603 6690,1440 r180 top
C500 "CGA6M3X7S2A475K200AB" 1210_220 4810,1140 r180 top
C501 "UCZ1J181MNQ1MS" UCZ_1250x1350 4310,1380 r270 top
C502 "CGA6M3X7S2A475K200AB" 1210_220 4640,1320 r270 top
C503 "GRM1885C1H391JA01D" 0603 4810,1050 r180 top
C504 "GCM188R71E105KA64D" 0603 6860,560 r180 top
C505 "GCM188R71E473KA37D" 0603 7320,570 r0 top
C506 "CGA6M3X7S2A475K200AB" 1210_220 7000,340 r0 top
C507 "GRM21BR72A103KA01L" 0805_HV 7020,450 r0 top
C508 "GCM188R72A332KA37D" 0603 7350,800 r180 top
C509 "GCM188R71H103KA37D" 0603 6860,680 r180 top
C510 "GCM188R71E105KA64D" 0603 7180,470 r180 top
C511 "GCM21BR71C475KA73K" 0805_HV 7180,400 r180 top
C512 "GCM21BC71C106KE36L" 0805_HV 7180,320 r180 top
C513 "GCM188R71H104KA57D" 0603 7260,770 r90 top
C514 "GCM1885C1H150JA16D" 0603 6990,1320 r180 top
C515 "GCM21BC71C106KE36L" 0805_HV 7160,930 r180 top
C516 "GCM188R71H104KA57D" 0603 7160,1000 r0 top
C517 "GCM21BC71C106KE36L" 0805_HV 7150,1210 r180 top
C518 "GCM21BC71C106KE36L" 0805_HV 7150,1300 r180 top
C519 "GCM188R71E105KA64D" 0603 7150,1560 r180 top
C520 "GCM188R71E105KA64D" 0603 7150,1390 r180 top
C600 "GCM188R71H103KA37D" 0603 3700,7690 r180 top
C601 "GCM188R71H103KA37D" 0603 3700,6180 r180 top
C602 "GCM188R71H103KA37D" 0603 3700,4670 r180 top
C603 "GCM188R71H103KA37D" 0603 3700,3160 r180 top
C604 "GCM188R71H104KA57D" 0603 7320,2090 r180 top
C800 "GCM188R71H103KA37D" 0603 7560,4460 r0 top
C801 "GCM188R71E105KA64D" 0603 6920,4340 r0 top
C802 "GCM188R71E105KA64D" 0603 7110,4760 r180 top
C803 "GCM188R70J225KE22D" 0603 7350,4160 r180 top
C804 "GCM188R70J225KE22D" 0603 7110,4640 r180 top
C805 "GCM188R71H104KA57D" 0603 7110,4700 r180 top
C806 "C1608C0G2A331J080AA" 0603 6890,3780 r0 top
C807 "GCM188R71H104KA57D" 0603 7210,3860 r180 top
C808 "C1608C0G2A331J080AA" 0603 7080,3560 r270 top
C809 "C1608C0G2A331J080AA" 0603 7350,3820 r180 top
C810 "C1608C0G2A331J080AA" 0603 7160,3560 r270 top
C811 "GCM188R71H104KA57D" 0603 7560,3640 r180 top
C812 "GCM188R71H104KA57D" 0603 7560,3810 r180 top
C900_LM1 "GCM1885C2A102JA16D" 0603 7000,2550 r90 top (schematic designator C900)
C900_LM2 "GCM1885C2A102JA16D" 0603 7000,5570 r90 top (schematic designator C900)
C901_LM1 "GRM188R71E154KA01D" 0603 6940,2550 r90 top (schematic designator C901)
C901_LM2 "GRM188R71E154KA01D" 0603 6940,5570 r90 top (schematic designator C901)
C902_LM1 "GCM1885C2A101JA16D" 0603 7490,2770 r0 top (schematic designator C902)
C902_LM2 "GCM1885C2A101JA16D" 0603 7490,5790 r0 top (schematic designator C902)
C903_LM1 "GCM188R71E473KA37D" 0603 7400,2680 r270 top (schematic designator C903)
C903_LM2 "GCM188R71E473KA37D" 0603 7400,5700 r270 top (schematic designator C903)
C904_LM1 "GCM1885C2A101JA16D" 0603 7490,2590 r180 top (schematic designator C904)
C904_LM2 "GCM1885C2A101JA16D" 0603 7490,5610 r180 top (schematic designator C904)
C905_LM1 "GCM1885C2A102JA16D" 0603 7140,3280 r90 top (schematic designator C905)
C905_LM2 "GCM1885C2A102JA16D" 0603 7140,6300 r90 top (schematic designator C905)
C906_LM1 "GCM1885C2A102JA16D" 0603 7060,2550 r270 top (schematic designator C906)
C906_LM2 "GCM1885C2A102JA16D" 0603 7060,5570 r270 top (schematic designator C906)
C907_LM1 "GRM31CR72A105KA01L" 1206_180 7270,3310 r90 top (schematic designator C907)
C907_LM2 "GRM31CR72A105KA01L" 1206_180 7270,6330 r90 top (schematic designator C907)
C908_LM1 "GCM188R71E474KA64D" 0603 6970,2780 r90 top (schematic designator C908)
C908_LM2 "GCM188R71E474KA64D" 0603 6970,5800 r90 top (schematic designator C908)
C909_LM1 "GCM188R71E105KA64D" 0603 7240,2550 r270 top (schematic designator C909)
C909_LM2 "GCM188R71E105KA64D" 0603 7240,5570 r270 top (schematic designator C909)
C910_LM1 "GCM21BR71C475KA73K" 0805_HV 6860,2930 r180 top (schematic designator C910)
C910_LM2 "GCM21BR71C475KA73K" 0805_HV 6860,5950 r180 top (schematic designator C910)
C911_LM1 "GCM188R71E474KA64D" 0603 6970,3100 r270 top (schematic designator C911)
C911_LM2 "GCM188R71E474KA64D" 0603 6970,6120 r270 top (schematic designator C911)
C912_LM1 "GCM188R72A332KA37D" 0603 7530,3050 r0 top (schematic designator C912)
C912_LM2 "GCM188R72A332KA37D" 0603 7530,6070 r0 top (schematic designator C912)
C913_LM1 "GCM188R71H103KA37D" 0603 6780,3280 r90 top (schematic designator C913)
C913_LM2 "GCM188R71H103KA37D" 0603 6780,6300 r90 top (schematic designator C913)
C914_LM1 "GCM1885C2A101JA16D" 0603 7490,3370 r0 top (schematic designator C914)
C914_LM2 "GCM1885C2A101JA16D" 0603 7490,6390 r0 top (schematic designator C914)
C915_LM1 "GCM188R71E473KA37D" 0603 7400,3280 r270 top (schematic designator C915)
C915_LM2 "GCM188R71E473KA37D" 0603 7400,6300 r270 top (schematic designator C915)
C916_LM1 "GCM1885C2A101JA16D" 0603 7490,3190 r180 top (schematic designator C916)
C916_LM2 "GCM1885C2A101JA16D" 0603 7490,6210 r180 top (schematic designator C916)
C917_LM1 "GRM188R71E154KA01D" 0603 6900,3280 r90 top (schematic designator C917)
C917_LM2 "GRM188R71E154KA01D" 0603 6900,6300 r90 top (schematic designator C917)
C918_LM1 "GCM1885C2A101JA16D" 0603 7080,3280 r90 top (schematic designator C918)
C918_LM2 "GCM1885C2A101JA16D" 0603 7080,6300 r90 top (schematic designator C918)
C919_LM1 "GCM1885C2A101JA16D" 0603 6820,2550 r270 top (schematic designator C919)
C919_LM2 "GCM1885C2A101JA16D" 0603 6820,5570 r270 top (schematic designator C919)
C920_LM1 "GCM1885C2A102JA16D" 0603 6960,3280 r90 top (schematic designator C920)
C920_LM2 "GCM1885C2A102JA16D" 0603 6960,6300 r90 top (schematic designator C920)
D100 "1N4148W-7-F" SOD-123 3210,1440 r180 top
D101 "BZX84C68LT1G" SOT-23 3600,1460 r90 top
D102 "1N4148W-7-F" SOD-123 3030,1440 r0 top
D103 "SMAJ78CA" SMA 3830,210 r225 top
D104 "5.0SMDJ78A" SMC 2950,400 r270 top
D105 "BZX84C68LT1G" SOT-23 3480,1460 r90 top
D106 "BAS516,115" SOD-523 3720,1430 r0 top
D107 "BAS516,115" SOD-523 3400,1740 r90 top
D400 "PMEG6010CEH,115" SOD-123F 4990,1170 r0 top
D401 "BZX384-C15,115" SOD-323 5100,980 r180 top
D402 "SMBJ28A-13-F" SMB 5160,370 r180 top
D403 "SMBJ24A-13-F" SMB 5160,210 r180 top
D500 "PMEG6010CEH,115" SOD-123F 4030,1750 r180 top
D501 "PMEG6010CEH,115" SOD-123F 4690,1450 r0 top
D502 "PMEG6010CEH,115" SOD-123F 7340,640 r180 top
D600 "1PS79SB70,115" SOD-523 7490,1920 r0 top
D601 "1PS79SB70,115" SOD-523 7490,1870 r0 top
D602 "1PS79SB70,115" SOD-523 7490,1820 r0 top
D603 "1PS79SB70,115" SOD-523 7070,1940 r270 top
D604 "1PS79SB70,115" SOD-523 7010,1940 r270 top
D700 "150060GS75000" WL-SMCW_GREEN 7560,3920 r180 top
D701 "150060GS75000" WL-SMCW_GREEN 7560,3870 r180 top
D800 "150060GS75000" WL-SMCW_GREEN 7770,3590 r180 top
D801 "150060YS75000" WL-SMCW_YELLOW 7770,3450 r0 top
D802 "150060SS75000" WL-SMCW_RED 7770,3310 r0 top
D803 "150060SS75000" WL-SMCW_RED 7770,3170 r0 top
D804 "150060SS75000" WL-SMCW_RED 7770,3030 r0 top
D900_LM1 "PMEG6010CEH,115" SOD-123F 6840,2800 r90 top (schematic designator D900)
D900_LM2 "PMEG6010CEH,115" SOD-123F 6840,5820 r90 top (schematic designator D900)
D901_LM1 "PMEG6010CEH,115" SOD-123F 6840,3080 r270 top (schematic designator D901)
D901_LM2 "PMEG6010CEH,115" SOD-123F 6840,6100 r270 top (schematic designator D901)
D902_LM1 "150060YS75000" WL-SMCW_YELLOW 7400,2560 r90 top (schematic designator D902)
D902_LM2 "150060YS75000" WL-SMCW_YELLOW 7400,5580 r90 top (schematic designator D902)
D903_LM1 "150060YS75000" WL-SMCW_YELLOW 7400,3400 r90 top (schematic designator D903)
D903_LM2 "150060YS75000" WL-SMCW_YELLOW 7400,6420 r90 top (schematic designator D903)
FID1 "Fiducial" Fiducial10-20 3940,1560 r0 top
FID2 "Fiducial" Fiducial10-20 7750,7750 r0 top
FID3 "Fiducial" Fiducial10-20 7740,140 r0 top
J1 "6095" Keystone_6095 4350,-200 r0 top
J2 "6095" Keystone_6095 5900,-200 r0 top
J3 "6095" Keystone_6095 3600,-200 r0 top
J4 "6095" Keystone_6095 5150,-200 r0 top
J700 "PRPC008DAAN-RC" Sullins_xxxC008DAAN 7750,1950 r0 top
J701 "PRPC008DAAN-RC" Sullins_xxxC008DAAN 7750,5050 r180 top
J702 "PRPC008DAAN-RC" Sullins_xxxC008DAAN 7750,4150 r180 top
J800 "TSM-107-01-L-DV" Samtec_TSM-107-01-x-DV 7200,5100 r270 top
L200 "XAL1060-401MEB" XAL1060 730,1560 r180 top
L201 "XAL1060-401MEB" XAL1060 730,1080 r180 top
L300_PS1 "IHTH1125KZEB4R7M5A" IHTH1125KZEB4R7 3710,2560 r180 top (schematic designator L300)
L300_PS1 "SER2915L-472KL" SER2915L 3710,2520 r270 top (schematic designator L300)
L300_PS2 "IHTH1125KZEB4R7M5A" IHTH1125KZEB4R7 3710,4070 r180 top (schematic designator L300)
L300_PS2 "SER2915L-472KL" SER2915L 3710,4030 r270 top (schematic designator L300)
L300_PS3 "IHTH1125KZEB4R7M5A" IHTH1125KZEB4R7 3710,5580 r180 top (schematic designator L300)
L300_PS3 "SER2915L-472KL" SER2915L 3710,5540 r270 top (schematic designator L300)
L300_PS4 "IHTH1125KZEB4R7M5A" IHTH1125KZEB4R7 3710,7090 r180 top (schematic designator L300)
L300_PS4 "SER2915L-472KL" SER2915L 3710,7050 r270 top (schematic designator L300)
L500 "MSS7341T-224MLB" MSS7341 4750,1660 r180 top
L501 "MSS1048-184KLB" MSS1048 7480,310 r270 top
L502 "MSS5121-333MLB" MSS5121 7350,1220 r90 top
L800 "BLM18AG121SN1D" 0603 7350,4100 r180 top
Logo2 "Pb-Free Symbol" Pb-Free_Overlay_Small 7350,7410 r90 top
Logo3 "FCC disclaimer" FCC_disclaimer 7740,7130 r90 top
MH1 "MTG_NoPads" NPTH125mil 2570,1560 r0 top locked
MH2 "MTG_NoPads" NPTH125mil 2890,3520 r0 top locked
MH3 "MTG_NoPads" NPTH125mil 260,1090 r0 top locked
MH4 "MTG_NoPads" NPTH125mil 5030,7190 r0 top locked
MH6 "MTG_NoPads" NPTH125mil 1410,5680 r0 top locked
MH7 "MTG_NoPads" NPTH125mil 2570,1080 r0 top locked
MH8 "MTG_NoPads" NPTH125mil 2890,5030 r0 top locked
MH9 "MTG_NoPads" NPTH125mil 1410,4170 r0 top locked
MH10 "MTG_NoPads" NPTH125mil 5600,600 r0 top locked
MH11 "MTG_NoPads" NPTH125mil 2890,2010 r0 top locked
MH12 "MTG_NoPads" NPTH125mil 5030,5680 r0 top locked
MH13 "MTG_NoPads" NPTH125mil 2890,6540 r0 top locked
MH14 "MTG_NoPads" NPTH125mil 1410,7190 r0 top locked
MH16 "MTG_NoPads" NPTH125mil 6420,600 r0 top locked
MH17 "MTG_NoPads" NPTH125mil 5030,2660 r0 top locked
MH18 "MTG_NoPads" NPTH125mil 5030,4170 r0 top locked
MH19 "MTG_NoPads" NPTH125mil 260,4170 r0 top locked
MH20 "MTG_NoPads" NPTH125mil 6400,2340 r0 top locked
MH21 "MTG_NoPads" NPTH125mil 1410,2660 r0 top locked
MH25 "MTG_NoPads" NPTH125mil 6400,3850 r0 top locked
MH26 "MTG_NoPads" NPTH125mil 6400,5360 r0 top locked
MH27 "MTG_NoPads" NPTH125mil 6400,6870 r0 top locked
MH28 "MTG_NoPads" NPTH125mil 260,7600 r0 top locked
NT1 "Net-Tie" Net-Tie_10mil 7610,2850 r180 top net-tie
Q100 "IPB180N10S402ATMA1" DDPAK-7 2130,1560 r270 top
Q101 "IPB180N10S402ATMA1" DDPAK-7 1240,1080 r90 top
Q102 "IPB180N10S402ATMA1" DDPAK-7 2130,1080 r270 top
Q103 "IPB180N10S402ATMA1" DDPAK-7 1240,1560 r90 top
Q104 "MMBTA06-7-F" SOT-23 3060,1560 r90 top
Q300_PS1 "TK65G10N1,RQ" DDPAK 1940,2580 r180 top (schematic designator Q300)
Q300_PS2 "TK65G10N1,RQ" DDPAK 1940,4090 r180 top (schematic designator Q300)
Q300_PS3 "TK65G10N1,RQ" DDPAK 1940,5600 r180 top (schematic designator Q300)
Q300_PS4 "TK65G10N1,RQ" DDPAK 1940,7110 r180 top (schematic designator Q300)
Q301_PS1 "TK65G10N1,RQ" DDPAK 1940,3020 r180 top (schematic designator Q301)
Q301_PS2 "TK65G10N1,RQ" DDPAK 1940,4530 r180 top (schematic designator Q301)
Q301_PS3 "TK65G10N1,RQ" DDPAK 1940,6040 r180 top (schematic designator Q301)
Q301_PS4 "TK65G10N1,RQ" DDPAK 1940,7550 r180 top (schematic designator Q301)
Q302_PS1 "TK65G10N1,RQ" DDPAK 2930,2770 r90 top (schematic designator Q302)
Q302_PS2 "TK65G10N1,RQ" DDPAK 2930,4280 r90 top (schematic designator Q302)
Q302_PS3 "TK65G10N1,RQ" DDPAK 2930,5790 r90 top (schematic designator Q302)
Q302_PS4 "TK65G10N1,RQ" DDPAK 2930,7300 r90 top (schematic designator Q302)
Q303_PS1 "TK65G10N1,RQ" DDPAK 2490,2770 r90 top (schematic designator Q303)
Q303_PS2 "TK65G10N1,RQ" DDPAK 2490,4280 r90 top (schematic designator Q303)
Q303_PS3 "TK65G10N1,RQ" DDPAK 2490,5790 r90 top (schematic designator Q303)
Q303_PS4 "TK65G10N1,RQ" DDPAK 2490,7300 r90 top (schematic designator Q303)
Q400 "SI2319DS-T1-E3" SOT-23 5100,1100 r90 top
Q401 "BC846B,215" SOT-23 4970,870 r270 top
Q402 "AUIRFS8409-7P" DDPAK-7 5460,1860 r0 top
Q403 "AUIRFS8409-7P" DDPAK-7 6420,970 r180 top
Q404 "AUIRFS8409-7P" DDPAK-7 5940,1860 r0 top
Q405 "AUIRFS8409-7P" DDPAK-7 5460,970 r180 top
Q406 "AUIRFS8409-7P" DDPAK-7 6420,1860 r0 top
Q407 "AUIRFS8409-7P" DDPAK-7 5940,970 r180 top
R100 "RC0603FR-07100KL" 0603 3720,1610 r0 top
R101 "RC0603FR-071KL" 0603 3720,1670 r0 top
R103 "RC0603FR-072K87L" 0603 3720,1490 r0 top
R104 "RC0603FR-0720K5L" 0603 3190,1580 r0 top
R105 "RC0603FR-072KL" 0603 3190,1520 r0 top
R106 "RC0603FR-07330KL" 0603 2960,1560 r90 top
R107 "RC0603FR-072K7L" 0603 3720,1550 r180 top
R108 "RC0603FR-07100KL" 0603 3720,1730 r180 top
R109 "RC0603JR-070RL" 0603 3120,1730 r90 top
R110 "RC0603JR-070RL" 0603 3180,1730 r90 top
R300_PS1 "PSR400ITQFH1L00" 3921_105 4540,2630 r0 top (schematic designator R300)
R300_PS2 "PSR400ITQFH1L00" 3921_105 4540,4140 r0 top (schematic designator R300)
R300_PS3 "PSR400ITQFH1L00" 3921_105 4540,5650 r0 top (schematic designator R300)
R300_PS4 "PSR400ITQFH1L00" 3921_105 4540,7160 r0 top (schematic designator R300)
R301_PS1 "RC0603FR-0751KL" 0603 2200,2610 r180 top (schematic designator R301)
R301_PS2 "RC0603FR-0751KL" 0603 2200,4120 r180 top (schematic designator R301)
R301_PS3 "RC0603FR-0751KL" 0603 2200,5630 r180 top (schematic designator R301)
R301_PS4 "RC0603FR-0751KL" 0603 2200,7140 r180 top (schematic designator R301)
R302_PS1 "RC0603FR-071RL" 0603 2200,2550 r0 top (schematic designator R302)
R302_PS2 "RC0603FR-071RL" 0603 2200,4060 r0 top (schematic designator R302)
R302_PS3 "RC0603FR-071RL" 0603 2200,5570 r0 top (schematic designator R302)
R302_PS4 "RC0603FR-071RL" 0603 2200,7080 r0 top (schematic designator R302)
R303_PS1 "CRCW121810R0FKEK" 1218 3270,3190 r90 top (schematic designator R303)
R303_PS2 "CRCW121810R0FKEK" 1218 3270,4700 r90 top (schematic designator R303)
R303_PS3 "CRCW121810R0FKEK" 1218 3270,6210 r90 top (schematic designator R303)
R303_PS4 "CRCW121810R0FKEK" 1218 3270,7720 r90 top (schematic designator R303)
R304_PS1 "RC0603FR-0751KL" 0603 2200,3050 r180 top (schematic designator R304)
R304_PS2 "RC0603FR-0751KL" 0603 2200,4560 r180 top (schematic designator R304)
R304_PS3 "RC0603FR-0751KL" 0603 2200,6070 r180 top (schematic designator R304)
R304_PS4 "RC0603FR-0751KL" 0603 2200,7580 r180 top (schematic designator R304)
R305_PS1 "RC0603FR-071RL" 0603 2200,2990 r0 top (schematic designator R305)
R305_PS2 "RC0603FR-071RL" 0603 2200,4500 r0 top (schematic designator R305)
R305_PS3 "RC0603FR-071RL" 0603 2200,6010 r0 top (schematic designator R305)
R305_PS4 "RC0603FR-071RL" 0603 2200,7520 r0 top (schematic designator R305)
R306_PS1 "RC0603FR-071RL" 0603 2900,2510 r90 top (schematic designator R306)
R306_PS2 "RC0603FR-071RL" 0603 2900,4020 r90 top (schematic designator R306)
R306_PS3 "RC0603FR-071RL" 0603 2900,5530 r90 top (schematic designator R306)
R306_PS4 "RC0603FR-071RL" 0603 2900,7040 r90 top (schematic designator R306)
R307_PS1 "RC0603FR-071RL" 0603 2460,2510 r90 top (schematic designator R307)
R307_PS2 "RC0603FR-071RL" 0603 2460,4020 r90 top (schematic designator R307)
R307_PS3 "RC0603FR-071RL" 0603 2460,5530 r90 top (schematic designator R307)
R307_PS4 "RC0603FR-071RL" 0603 2460,7040 r90 top (schematic designator R307)
R308_PS1 "RC0603FR-0751KL" 0603 2960,2510 r270 top (schematic designator R308)
R308_PS2 "RC0603FR-0751KL" 0603 2960,4020 r270 top (schematic designator R308)
R308_PS3 "RC0603FR-0751KL" 0603 2960,5530 r270 top (schematic designator R308)
R308_PS4 "RC0603FR-0751KL" 0603 2960,7040 r270 top (schematic designator R308)
R309_PS1 "RC0603FR-0751KL" 0603 2520,2510 r270 top (schematic designator R309)
R309_PS2 "RC0603FR-0751KL" 0603 2520,4020 r270 top (schematic designator R309)
R309_PS3 "RC0603FR-0751KL" 0603 2520,5530 r270 top (schematic designator R309)
R309_PS4 "RC0603FR-0751KL" 0603 2520,7040 r270 top (schematic designator R309)
R400 "RC0603FR-07100KL" 0603 5100,920 r0 top
R401 "RC0603FR-0710KL" 0603 5100,860 r0 top
R402 "RC0603FR-0710KL" 0603 4970,1040 r0 top
R403 "RC0603FR-0710KL" 0603 4970,980 r0 top
R404 "RC0603FR-07220KL" 0603 6690,1380 r180 top
R405 "RC0603JR-070RL" 0603 6720,1780 r0 top
R406 "RC0603JR-070RL" 0603 6720,1840 r0 top
R500 "CSR1206FKR500" 1206 4880,1460 r0 top
R501 "5106" 5106 5100,1400 r90 top
R502 "CRCW0603180RJNEA" 0603 5010,1470 r270 top
R503 "RC0603FR-0747KL" 0603 5070,1300 r0 top
R504 "RC0603FR-072K2L" 0603 5070,1240 r180 top
R505 "RC0603FR-07169KL" 0603 6860,620 r0 top
R506 "5106" 5106 7320,920 r180 top
R507 "RC0603FR-0710KL" 0603 7170,800 r180 top
R508 "RC0603FR-07100KL" 0603 7350,740 r180 top
R509 "RC0603FR-073K32L" 0603 7170,740 r180 top
R510 "5106" 5106 7260,1480 r90 top
R511 "RC0603FR-0710KL" 0603 6990,1260 r180 top
R512 "RC0603FR-073K16L" 0603 6990,1200 r0 top
R600 "RC0603FR-0710KL" 0603 7490,2040 r180 top
R601 "RC0603FR-0710KL" 0603 7490,1760 r180 top
R602 "RC0603FR-078K2L" 0603 7010,2060 r90 top
R603 "RC0603JR-070RL" 0603 7200,2090 r0 top
R604 "RC0603FR-077K5L" 0603 7070,2060 r270 top
R605 "RC0603FR-07680RL" 0603 7340,1790 r270 top
R606 "RC0603FR-07100KL" 0603 7280,1790 r270 top
R607 "RC0603FR-07102KL" 0603 7040,1860 r180 top
R608 "RC0603FR-0710KL" 0603 7490,1980 r0 top
R700 "RC0603FR-07680RL" 0603 7560,3980 r180 top
R701 "RC0603FR-07680RL" 0603 7560,4040 r180 top
R800 "RC0603FR-074K7L" 0603 6830,5170 r90 top
R801 "RC0603FR-07680RL" 0603 7770,3530 r180 top
R802 "RC0603FR-071K5L" 0603 7770,3250 r180 top
R803 "RC0603FR-074K7L" 0603 6830,5040 r270 top
R804 "RC0603FR-072K55L" 0603 7560,4400 r180 top
R805 "RC0603FR-074K7L" 0603 7570,5120 r270 top
R806 "RC0603FR-071K5L" 0603 7770,3390 r180 top
R807 "RC0603FR-07680RL" 0603 7350,4040 r180 top
R808 "RC0603FR-0710KL" 0603 6910,4420 r180 top
R809 "RC0603FR-0710KL" 0603 6910,4480 r180 top
R810 "RC0603FR-0722RL" 0603 7290,4730 r270 top
R811 "RC0603FR-0722RL" 0603 7350,4730 r270 top
R812 "RT0603DRE0730K1L" 0603 6890,3720 r180 top
R813 "RT0603DRE071KL" 0603 6890,3840 r180 top
R814 "RC0603FR-0722RL" 0603 7470,4730 r270 top
R815 "RC0603FR-0722RL" 0603 7410,4730 r270 top
R816 "RC0603FR-0722RL" 0603 6920,4280 r0 top
R817 "RC0603FR-0710KL" 0603 7010,4730 r90 top
R818 "RC0603FR-0710KL" 0603 7040,4820 r180 top
R819 "RT0603DRE0730K1L" 0603 6890,3660 r180 top
R820 "RC0603FR-0722RL" 0603 6920,4220 r0 top
R821 "RC0603FR-0722RL" 0603 7040,4160 r180 top
R822 "RT0603DRE071KL" 0603 7020,3560 r270 top
R823 "RC0603FR-0722RL" 0603 7040,4080 r180 top
R824 "RC0603FR-0722RL" 0603 7560,4100 r0 top
R825 "RC0603FR-0722RL" 0603 7560,4160 r0 top
R826 "RC0603FR-0722RL" 0603 7560,4220 r0 top
R827 "RC0603FR-0722RL" 0603 7560,4280 r0 top
R828 "RC0603FR-0722RL" 0603 7560,4340 r0 top
R829 "RT0603DRE0710KL" 0603 7350,3700 r0 top
R830 "RT0603DRE071KL" 0603 7350,3760 r0 top
R831 "RT0603DRE0710KL" 0603 7350,3640 r0 top
R832 "RT0603DRE071KL" 0603 7220,3560 r270 top
R833 "RC0603FR-071K5L" 0603 7770,3110 r180 top
R834 "RC0603FR-071K5L" 0603 7770,2970 r180 top
R835 "RC0603FR-0710KL" 0603 6740,3930 r90 top
R836 "RC0603FR-0710KL" 0603 6800,3930 r90 top
R900_LM1 "RC0603FR-07634RL" 0603 6880,2550 r270 top (schematic designator R900)
R900_LM2 "RC0603FR-07634RL" 0603 6880,5570 r270 top (schematic designator R900)
R901_LM1 "RC0603FR-0710RL" 0603 7490,2710 r0 top (schematic designator R901)
R901_LM2 "RC0603FR-0710RL" 0603 7490,5730 r0 top (schematic designator R901)
R902_LM1 "RC0603FR-0795K3L" 0603 7200,3280 r90 top (schematic designator R902)
R902_LM2 "RC0603FR-0795K3L" 0603 7200,6300 r90 top (schematic designator R902)
R903_LM1 "RC0603FR-0795K3L" 0603 7120,2550 r270 top (schematic designator R903)
R903_LM2 "RC0603FR-0795K3L" 0603 7120,5570 r270 top (schematic designator R903)
R904_LM1 "RC0603FR-0710RL" 0603 7490,2650 r0 top (schematic designator R904)
R904_LM2 "RC0603FR-0710RL" 0603 7490,5670 r0 top (schematic designator R904)
R905_LM1 "RC0603FR-0710KL" 0603 7400,3160 r270 top (schematic designator R905)
R905_LM2 "RC0603FR-0710KL" 0603 7400,6180 r270 top (schematic designator R905)
R906_LM1 "RC0603FR-0710KL" 0603 7620,3080 r90 top (schematic designator R906)
R906_LM2 "RC0603FR-0710KL" 0603 7620,6100 r90 top (schematic designator R906)
R907_LM1 "RC0603FR-072RL" 0603 6910,2780 r270 top (schematic designator R907)
R907_LM2 "RC0603FR-072RL" 0603 6910,5800 r270 top (schematic designator R907)
R908_LM1 "RC0603FR-0710KL" 0603 7590,2890 r180 top (schematic designator R908)
R908_LM2 "RC0603FR-0710KL" 0603 7590,5910 r180 top (schematic designator R908)
R909_LM1 "RC0603FR-0740K2L" 0603 7530,3110 r180 top (schematic designator R909)
R909_LM2 "RC0603FR-0740K2L" 0603 7530,6130 r180 top (schematic designator R909)
R910_LM1 "RC0603FR-0724RL" 0603 7300,2550 r270 top (schematic designator R910)
R910_LM2 "RC0603FR-0724RL" 0603 7300,5570 r270 top (schematic designator R910)
R911_LM1 "RC0603FR-0710KL" 0603 7590,2950 r180 top (schematic designator R911)
R911_LM2 "RC0603FR-0710KL" 0603 7590,5970 r180 top (schematic designator R911)
R912_LM1 "RC0603FR-0740K2L" 0603 7180,2550 r90 top (schematic designator R912)
R912_LM2 "RC0603FR-0740K2L" 0603 7180,5570 r90 top (schematic designator R912)
R913_LM1 "RC0603FR-072RL" 0603 6910,3100 r90 top (schematic designator R913)
R913_LM2 "RC0603FR-072RL" 0603 6910,6120 r90 top (schematic designator R913)
R914_LM1 "RC0603FR-0710RL" 0603 7490,3310 r0 top (schematic designator R914)
R914_LM2 "RC0603FR-0710RL" 0603 7490,6330 r0 top (schematic designator R914)
R915_LM1 "RC0603FR-0710RL" 0603 7490,3250 r0 top (schematic designator R915)
R915_LM2 "RC0603FR-0710RL" 0603 7490,6270 r0 top (schematic designator R915)
R916_LM1 "RC0603FR-071K5L" 0603 7490,2530 r180 top (schematic designator R916)
R916_LM2 "RC0603FR-071K5L" 0603 7490,5550 r180 top (schematic designator R916)
R917_LM1 "RC0603FR-071K5L" 0603 7490,3430 r0 top (schematic designator R917)
R917_LM2 "RC0603FR-071K5L" 0603 7490,6450 r0 top (schematic designator R917)
R918_LM1 "RC0603FR-0764K9L" 0603 7020,3280 r270 top (schematic designator R918)
R918_LM2 "RC0603FR-0764K9L" 0603 7020,6300 r270 top (schematic designator R918)
R919_LM1 "RC0603FR-0764K9L" 0603 6760,2550 r90 top (schematic designator R919)
R919_LM2 "RC0603FR-0764K9L" 0603 6760,5570 r90 top (schematic designator R919)
R920_LM1 "RC0603FR-07634RL" 0603 6840,3280 r270 top (schematic designator R920)
R920_LM2 "RC0603FR-07634RL" 0603 6840,6300 r270 top (schematic designator R920)
RV400 "V20P17AUTO" Littelfuse_V20P17AUTO 5060,550 r0 top
S800 "218-2LPST" SW_218-2LP 6770,4180 r270 top
TP100 "TESTPOINT" TP_60MIL-SMT 3330,1650 r90 top
U100 "LM5060Q1MMX/NOPB" MUB10A_N 3530,1620 r180 top
U500 "MC33063AQDRQ1" D0008A_N 4860,1310 r0 top
U501 "LM5010AQ1MH/NOPB" MXA14A_N 7100,600 r180 top
U502 "TPS560200QDGKRQ1" DGK0008A_M 7100,1100 r0 top
U503 "LP5912Q3.3DRVRQ1" DRV0006A 7160,1480 r270 top
U600 "TMP102AQDRLRQ1" DRL0006A 3710,7760 r270 top
U601 "TPS3306-33QDRQ1" D0008A_N 7260,1960 r0 top
U602 "TMP102AQDRLRQ1" DRL0006A 3710,6250 r270 top
U603 "TMP102AQDRLRQ1" DRL0006A 3710,4740 r270 top
U604 "TL431AQDBZRQ1" DBZ0003A_N 7170,1790 r180 top
U605 "TMP102AQDRLRQ1" DRL0006A 3710,3230 r270 top
U800 "SN74LVC2G17QDCKRQ1" DCK0006A_N 7560,3740 r0 top
U801 "TMS320F28027FPTQ" PT0048A_N 7200,4390 r90 top
U802 "TL431AQDBZRQ1" DBZ0003A_N 7330,3940 r0 top
U803 "TLC2272AQDRQ1A" D0008A_N 7120,3730 r0 top
U804 "SN74LVC2G17QDCKRQ1" DCK0006A_N 7560,3570 r0 top
U900_LM1 "LM5170QPHPRQ1" PHP0048D_N 7210,2940 r270 top (schematic designator U900)
U900_LM2 "LM5170QPHPRQ1" PHP0048D_N 7210,5960 r270 top (schematic designator U900)
ZZ1 "This Assembly Note is for PCB labels only" AssemblyNoteLabel 8200,6120 r0 top
ZZ2 "These assemblies are ESD sensitive, ESD precautions shall be observed." AssemblyNote 8200,6280 r0 top
ZZ3 "These assemblies must be clean and free from flux and all contaminants. Use of no clean flux is not acceptable." AssemblyNote 8200,6440 r0 top
ZZ4 "These assemblies must comply with workmanship standards IPC-A-610 Class 2, unless otherwise specified." AssemblyNote 8200,6360 r0 top

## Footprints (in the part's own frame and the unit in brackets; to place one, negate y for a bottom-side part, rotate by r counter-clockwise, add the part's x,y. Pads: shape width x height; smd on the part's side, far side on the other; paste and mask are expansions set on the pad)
0603 [mm] "0603 from SM-752 data"
  rect 1x0.95 smd: 1(-0.8,0) 2(0.8,0)
  silkscreen extent -1.52,-0.69 1.52,0.69, body extent -0.87,-0.47 0.87,0.47, height 1
0805_HV [mil] "0805 with 30mil clearance between pads"
  rect 50x63 smd: 1(-40,0) 2(40,0)
  silkscreen extent -74,-40 74,40, body extent -43,-29 43,29, height 57
1206 [mm] "1206 from SM-752 data"
  rect 1.3x1.85 smd: 1(-1.45,0) 2(1.45,0)
  silkscreen extent -2.4,-1.21 2.4,1.21, body extent -1.7,-0.9 1.7,0.9, height 1.35
1206_180 [mm] "1206_180"
  rect 1.1x1.6 smd: 1(-1.7,0) 2(1.7,0)
  silkscreen extent -0.9,-1 0.9,1, body extent -1.75,-0.95 1.75,0.95, height 1.8
1210_220 [mm] "1210"
  rect 1.3x2.7 smd: 1(-1.45,0) 2(1.45,0)
  silkscreen extent -2.32,-1.57 2.32,1.57, body extent -1.7,-1.35 1.7,1.35, height 2.2
1210_220L [mm] "1210"
  rect 1.1x2.6 smd: 1(-1.35,0) 2(1.35,0)
  silkscreen extent -0.4,-1.2 0.4,1.2, body extent -1.7,-1.35 1.7,1.35, height 2.2
1210_280 [mm] "SMD, 2-Leads, Body 3.6x2.8mm, Height 2.8mm"
  rect 1.1x2.2 smd: 1(-1.65,0) 2(1.65,0)
  silkscreen extent -0.84,-1.4 0.84,1.4, body extent -1.8,-1.4 1.8,1.4, height 2.8
1218 [mil] "Vishay recommended land pattern for 1218, document number 20008 revision 13-Oct-08"
  rect 40x187 smd: 1(-59,0) 2(59,0)
  silkscreen extent -94,-110 94,110, body extent -65,-93 65,93, height 24
2220_250 [mm] "2220"
  rect 1.6x5.3 smd: 1(-2.6,0) 2(2.6,0)
  silkscreen extent -3.69,-2.94 3.69,2.94, body extent -2.95,-2.62 2.95,2.62, height 2.5
3921_105 [mm] "SMD, 2-Leads, Body 10x5.2mm"
  rect 2.7x6.2 smd: 1(-4.15,0) 2(4.15,0)
  silkscreen extent -2.4,-2.75 2.4,2.75, body extent -5.15,-2.75 5.15,2.75, height 1.05
5106 [mm] "Keystone"
  rect 0.99x1.4 smd: 1(-0.85,0) 2(0.88,0)
  silkscreen extent -1.63,-0.97 1.65,0.97, body extent -1.06,-0.69 1.06,0.69, height 0.84
AssemblyNote [mil] "Assembly Note"
AssemblyNoteLabel [mil] "Assembly Note for PCB Labels"
D0008A_N [mm] "SOIC, 8-Leads, Body 4.9x3.9mm, Pitch 1.27mm, IPC Medium Density"
  oval 1.45x0.6 smd: 1(-2.725,1.905) 2(-2.725,0.635) 3(-2.725,-0.635) 4(-2.725,-1.905) 5(2.725,-1.905) 6(2.725,-0.635) 7(2.725,0.635) 8(2.725,1.905)
  silkscreen extent -3.3,-2.5 0.9,2.5, body extent -3,-2.45 3,2.45, height 1.63
DBZ0003A_N [mm] "SOT23, 3-Leads, Body 2.9x1.3mm, Pitch 0.95mm, Lead Span 2.4mm, IPC Medium Density"
  rrect17% 1x0.6 smd: 1(-1.2,0.95) 2(-1.2,-0.95) 3(1.2,0)
  silkscreen extent -1.65,-1.5 0.7,1.5, body extent -1.26,-1.46 1.26,1.46, height 0.98
DCK0006A_N [mm] "SOT23, 6-Leads, Body 2x1.3mm, Pitch 0.65mm, Lead Span 2.1mm, IPC Medium Density"
  rrect25% 0.85x0.4 smd: 1(-1.125,0.65) 2(-1.125,0) 3(-1.125,-0.65) 4(1.125,-0.65) 5(1.125,0) 6(1.125,0.65)
  silkscreen extent -1.5,-1.09 0.51,1.09, body extent -1.14,-1 1.14,1, height 0.95
DDPAK [mil] "D2-PAK, 3-Pads, Body 9.7x10.4mm (max), TO-263AB, using Vishay Silionix recommended pad sizes"
  rrect8% 135x49.49 smd: 1(-246.06,100) 3(-246.06,-100)
  rrect1% 355x420 smd paste-181.1: 4(155.51,0)
  silkscreen extent -295,-220 344,220, body extent -295,-202 324,202, height 180
DDPAK-7 [mil]
  rect 38x138 smd: 1(-150,-347) 2(-100,-347) 3(-50,-347) 5(50,-347) 6(100,-347) 7(150,-347)
  rect 420x458 smd: 4(0,6)
  silkscreen extent -168,-264 168,-247, body extent -210,-386 210,240, height 190
DGK0008A_M [mm] "TSOP, 8-Leads, Body 3x3mm, Pitch 0.65mm, IPC Low Density"
  oval 1.55x0.45 smd: 1(-2.325,0.975) 2(-2.325,0.325) 3(-2.325,-0.325) 4(-2.325,-0.975) 5(2.325,-0.975) 6(2.325,-0.325) 7(2.325,0.325) 8(2.325,0.975)
  silkscreen extent -2.88,-1.55 0.85,1.55, body extent -2.45,-1.5 2.45,1.5, height 0.96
